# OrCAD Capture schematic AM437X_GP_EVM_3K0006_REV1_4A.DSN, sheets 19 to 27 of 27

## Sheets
19 Pg27: Power Monitor: size C
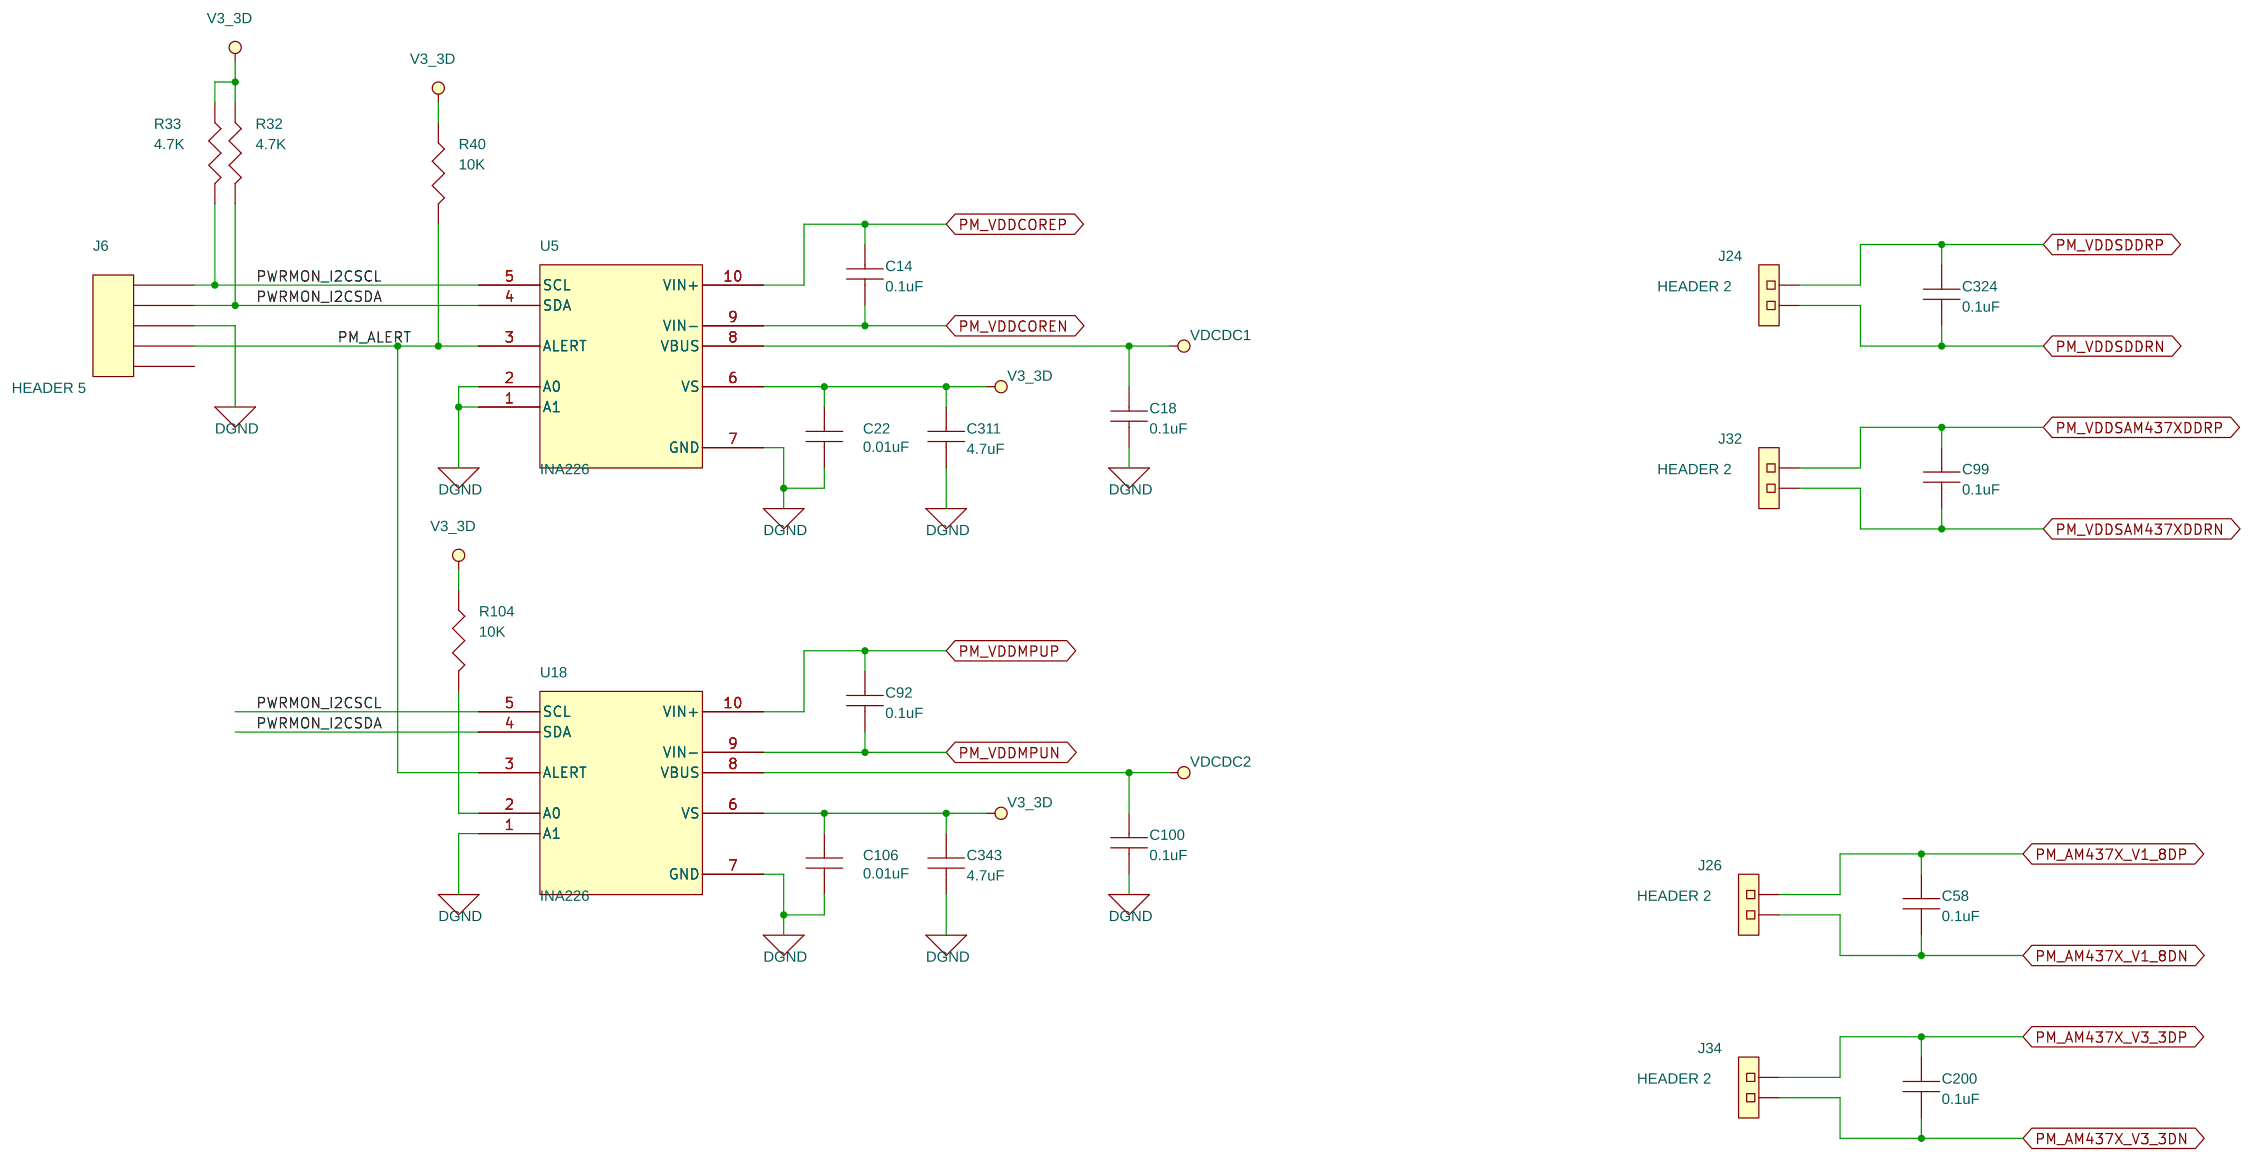
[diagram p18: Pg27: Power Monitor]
20 Pg19: Wireless COM8: size C
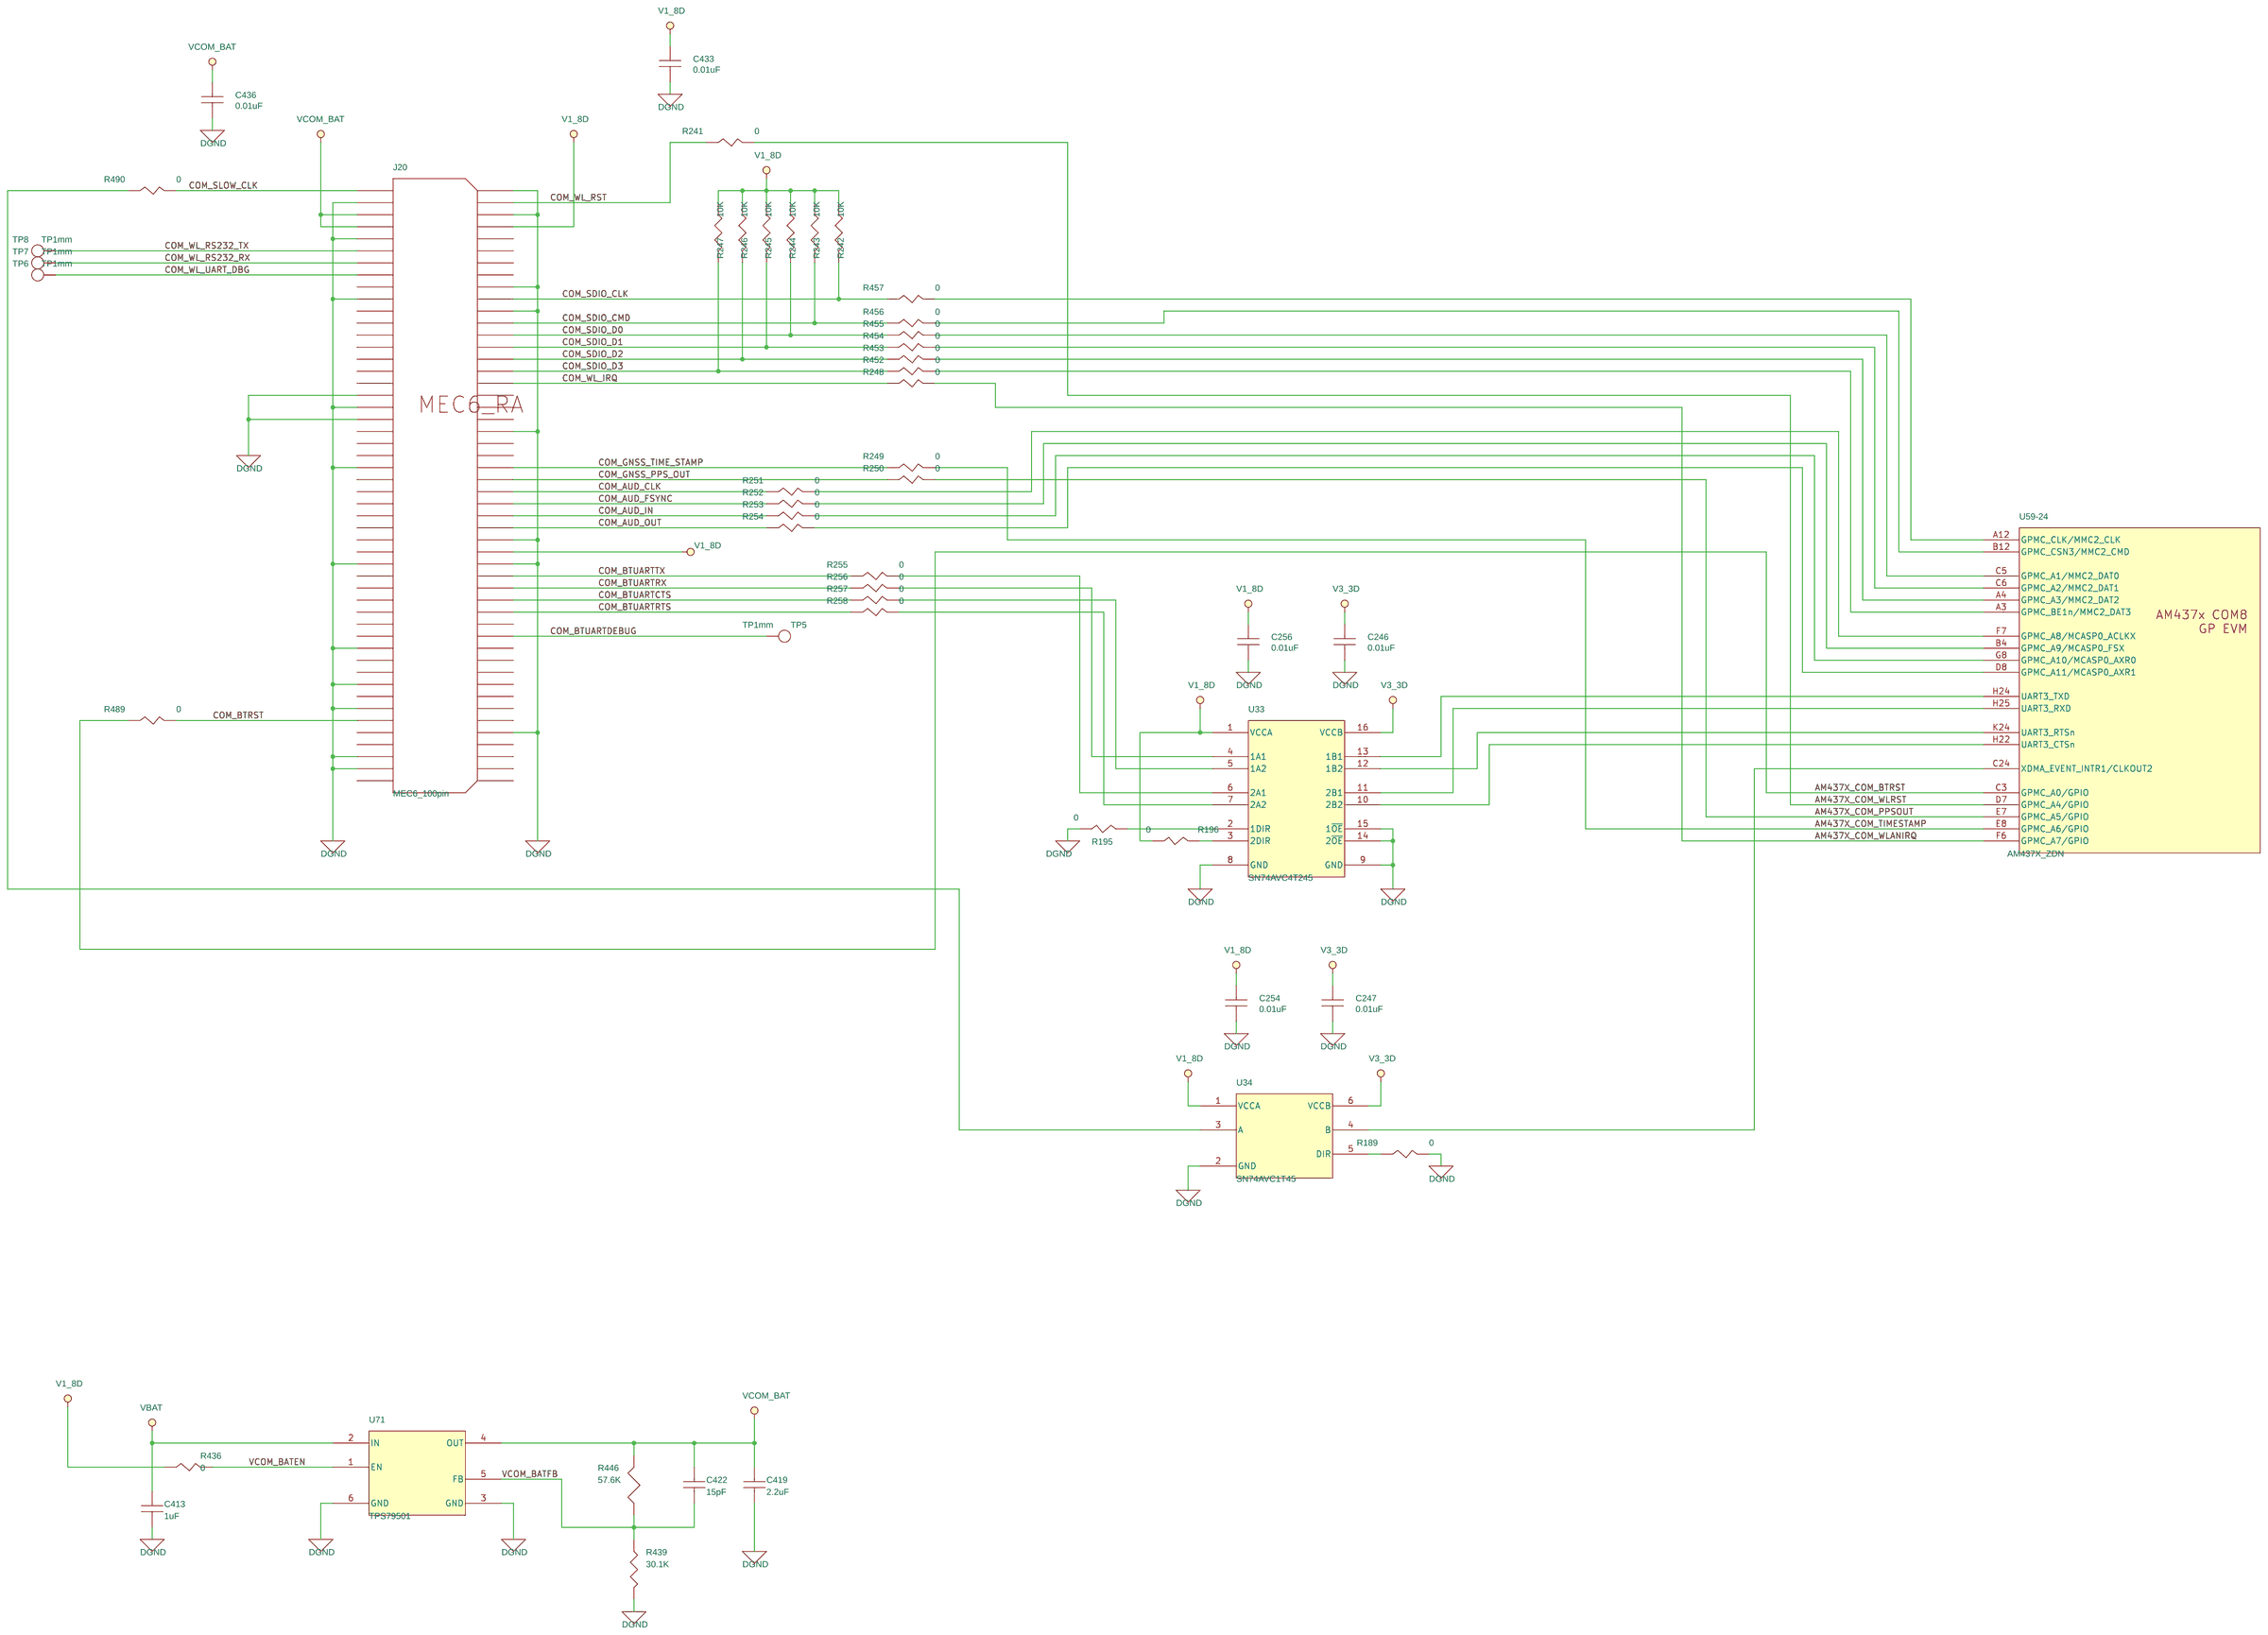
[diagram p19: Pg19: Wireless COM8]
21 Pg04: Power Supply - PMIC: size C
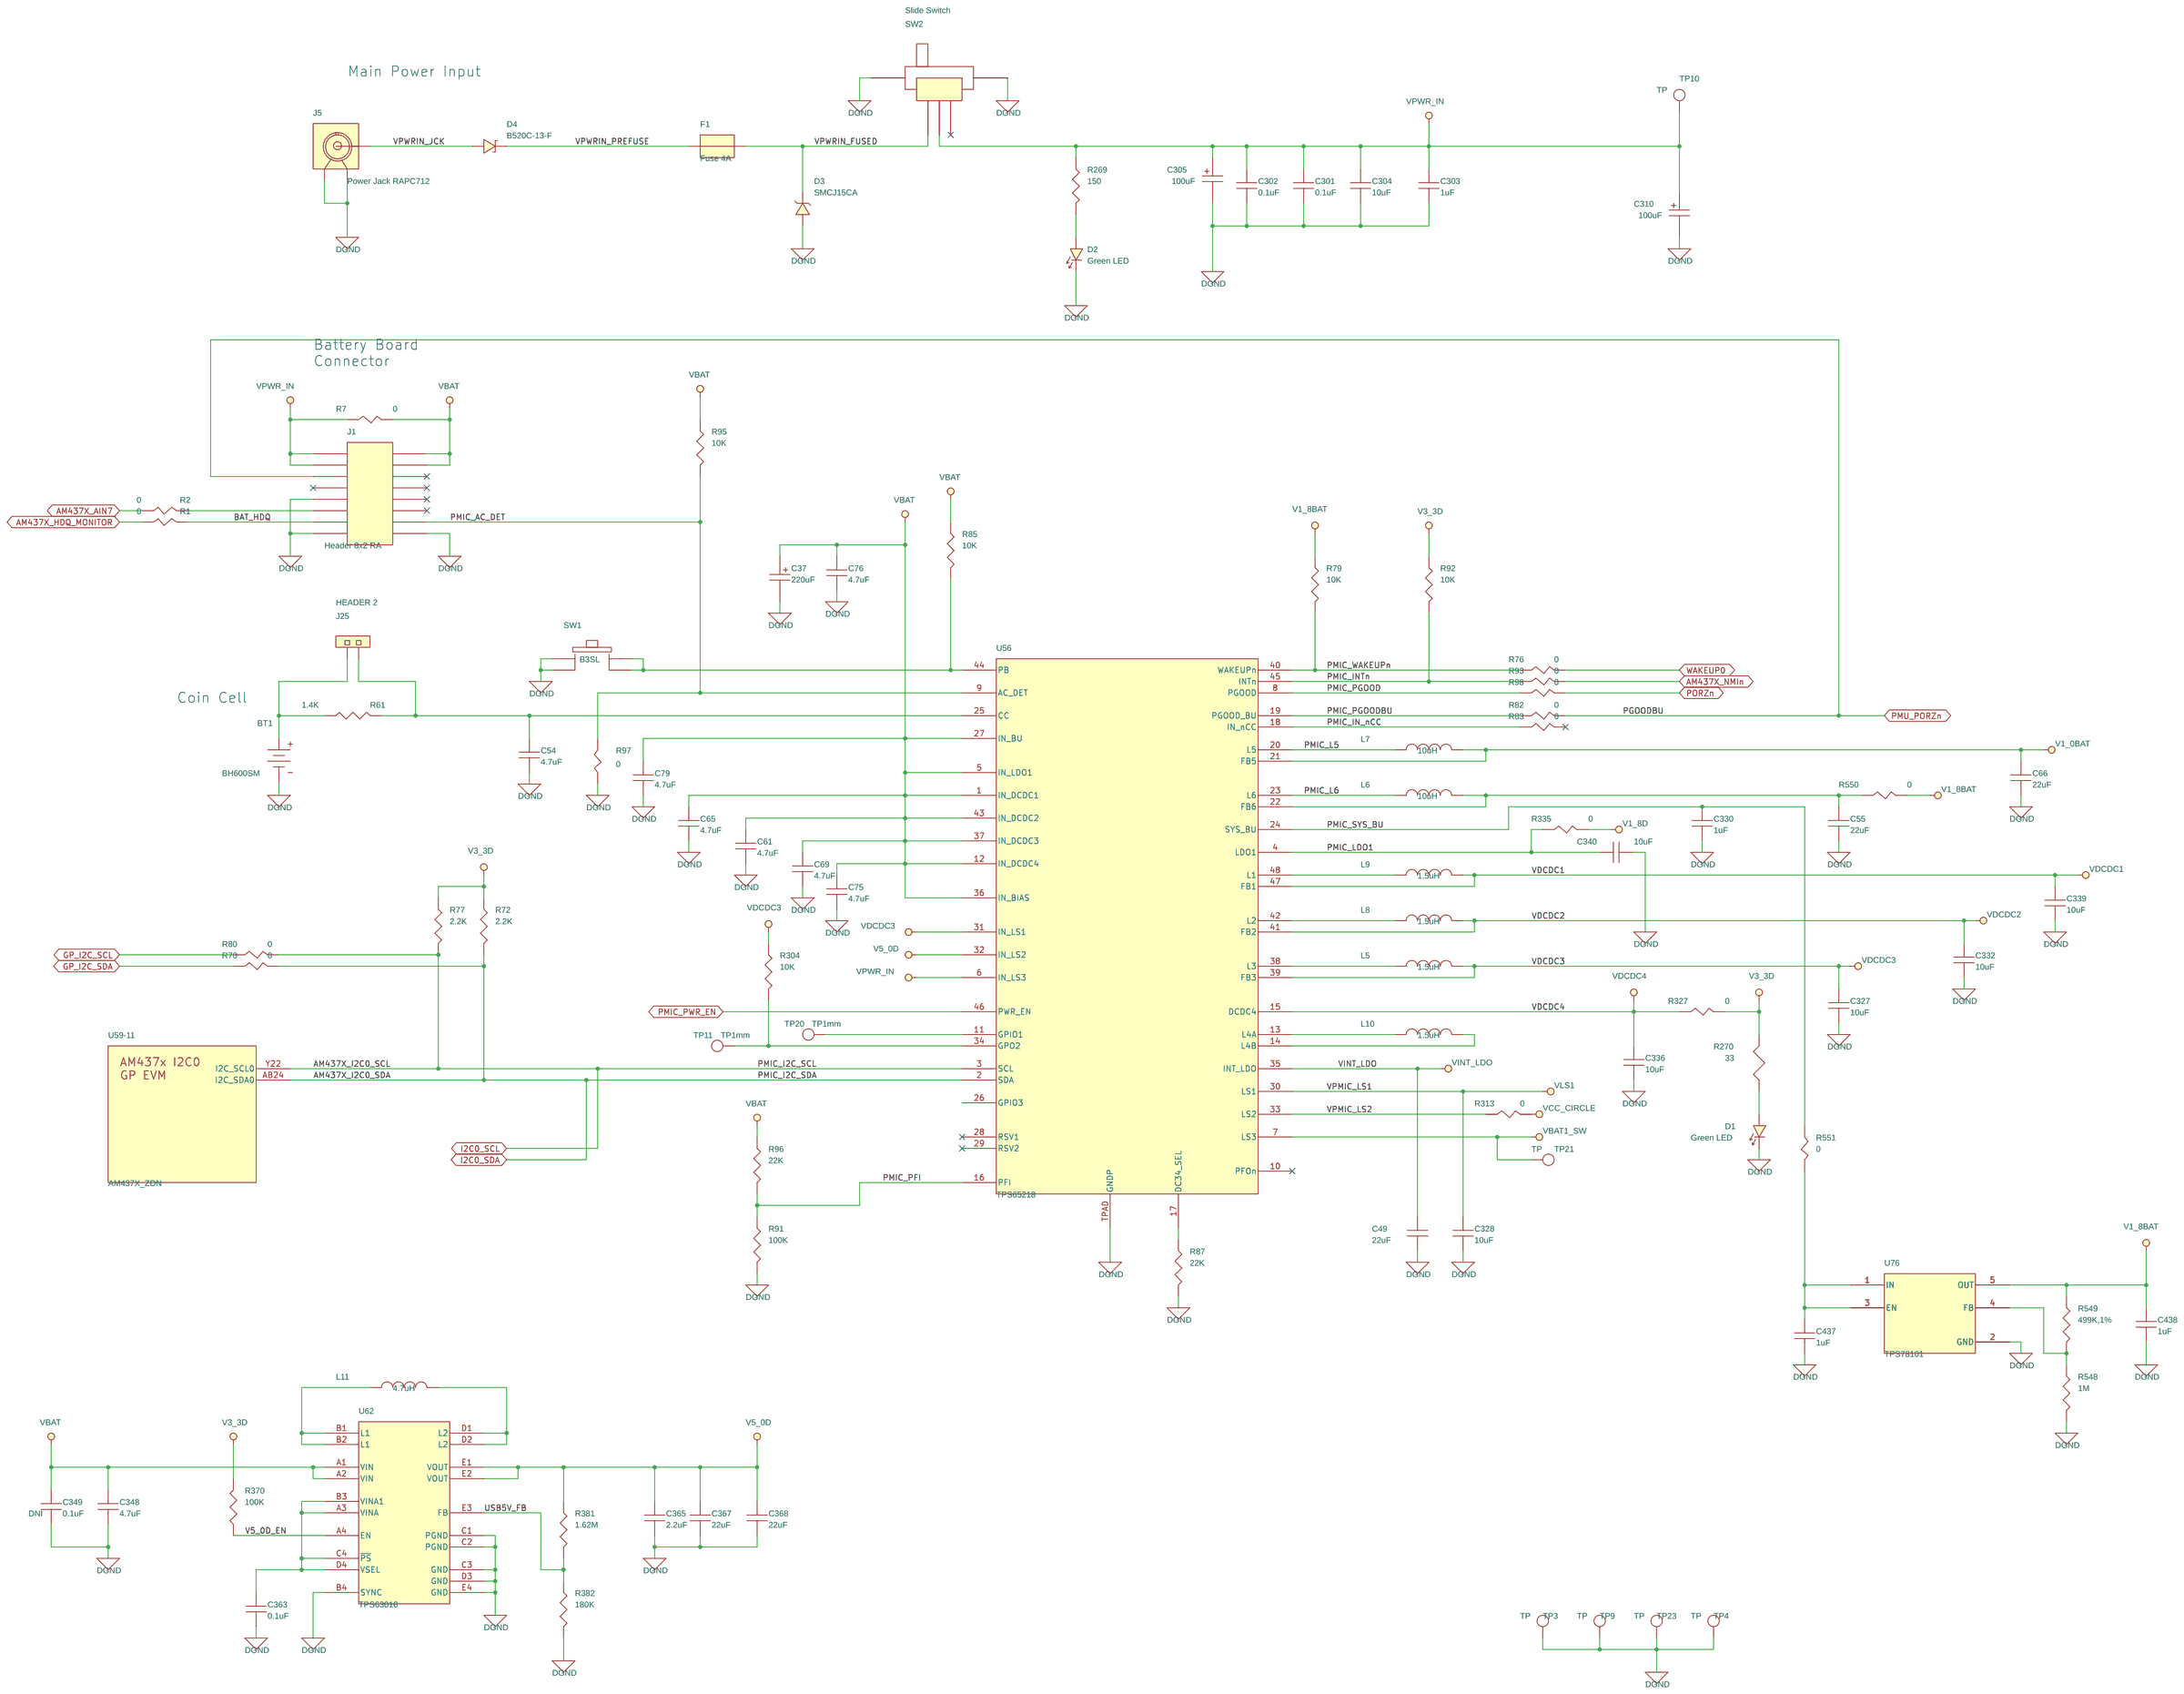
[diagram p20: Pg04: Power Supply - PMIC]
22 Pg02: Processor subsystem: size C
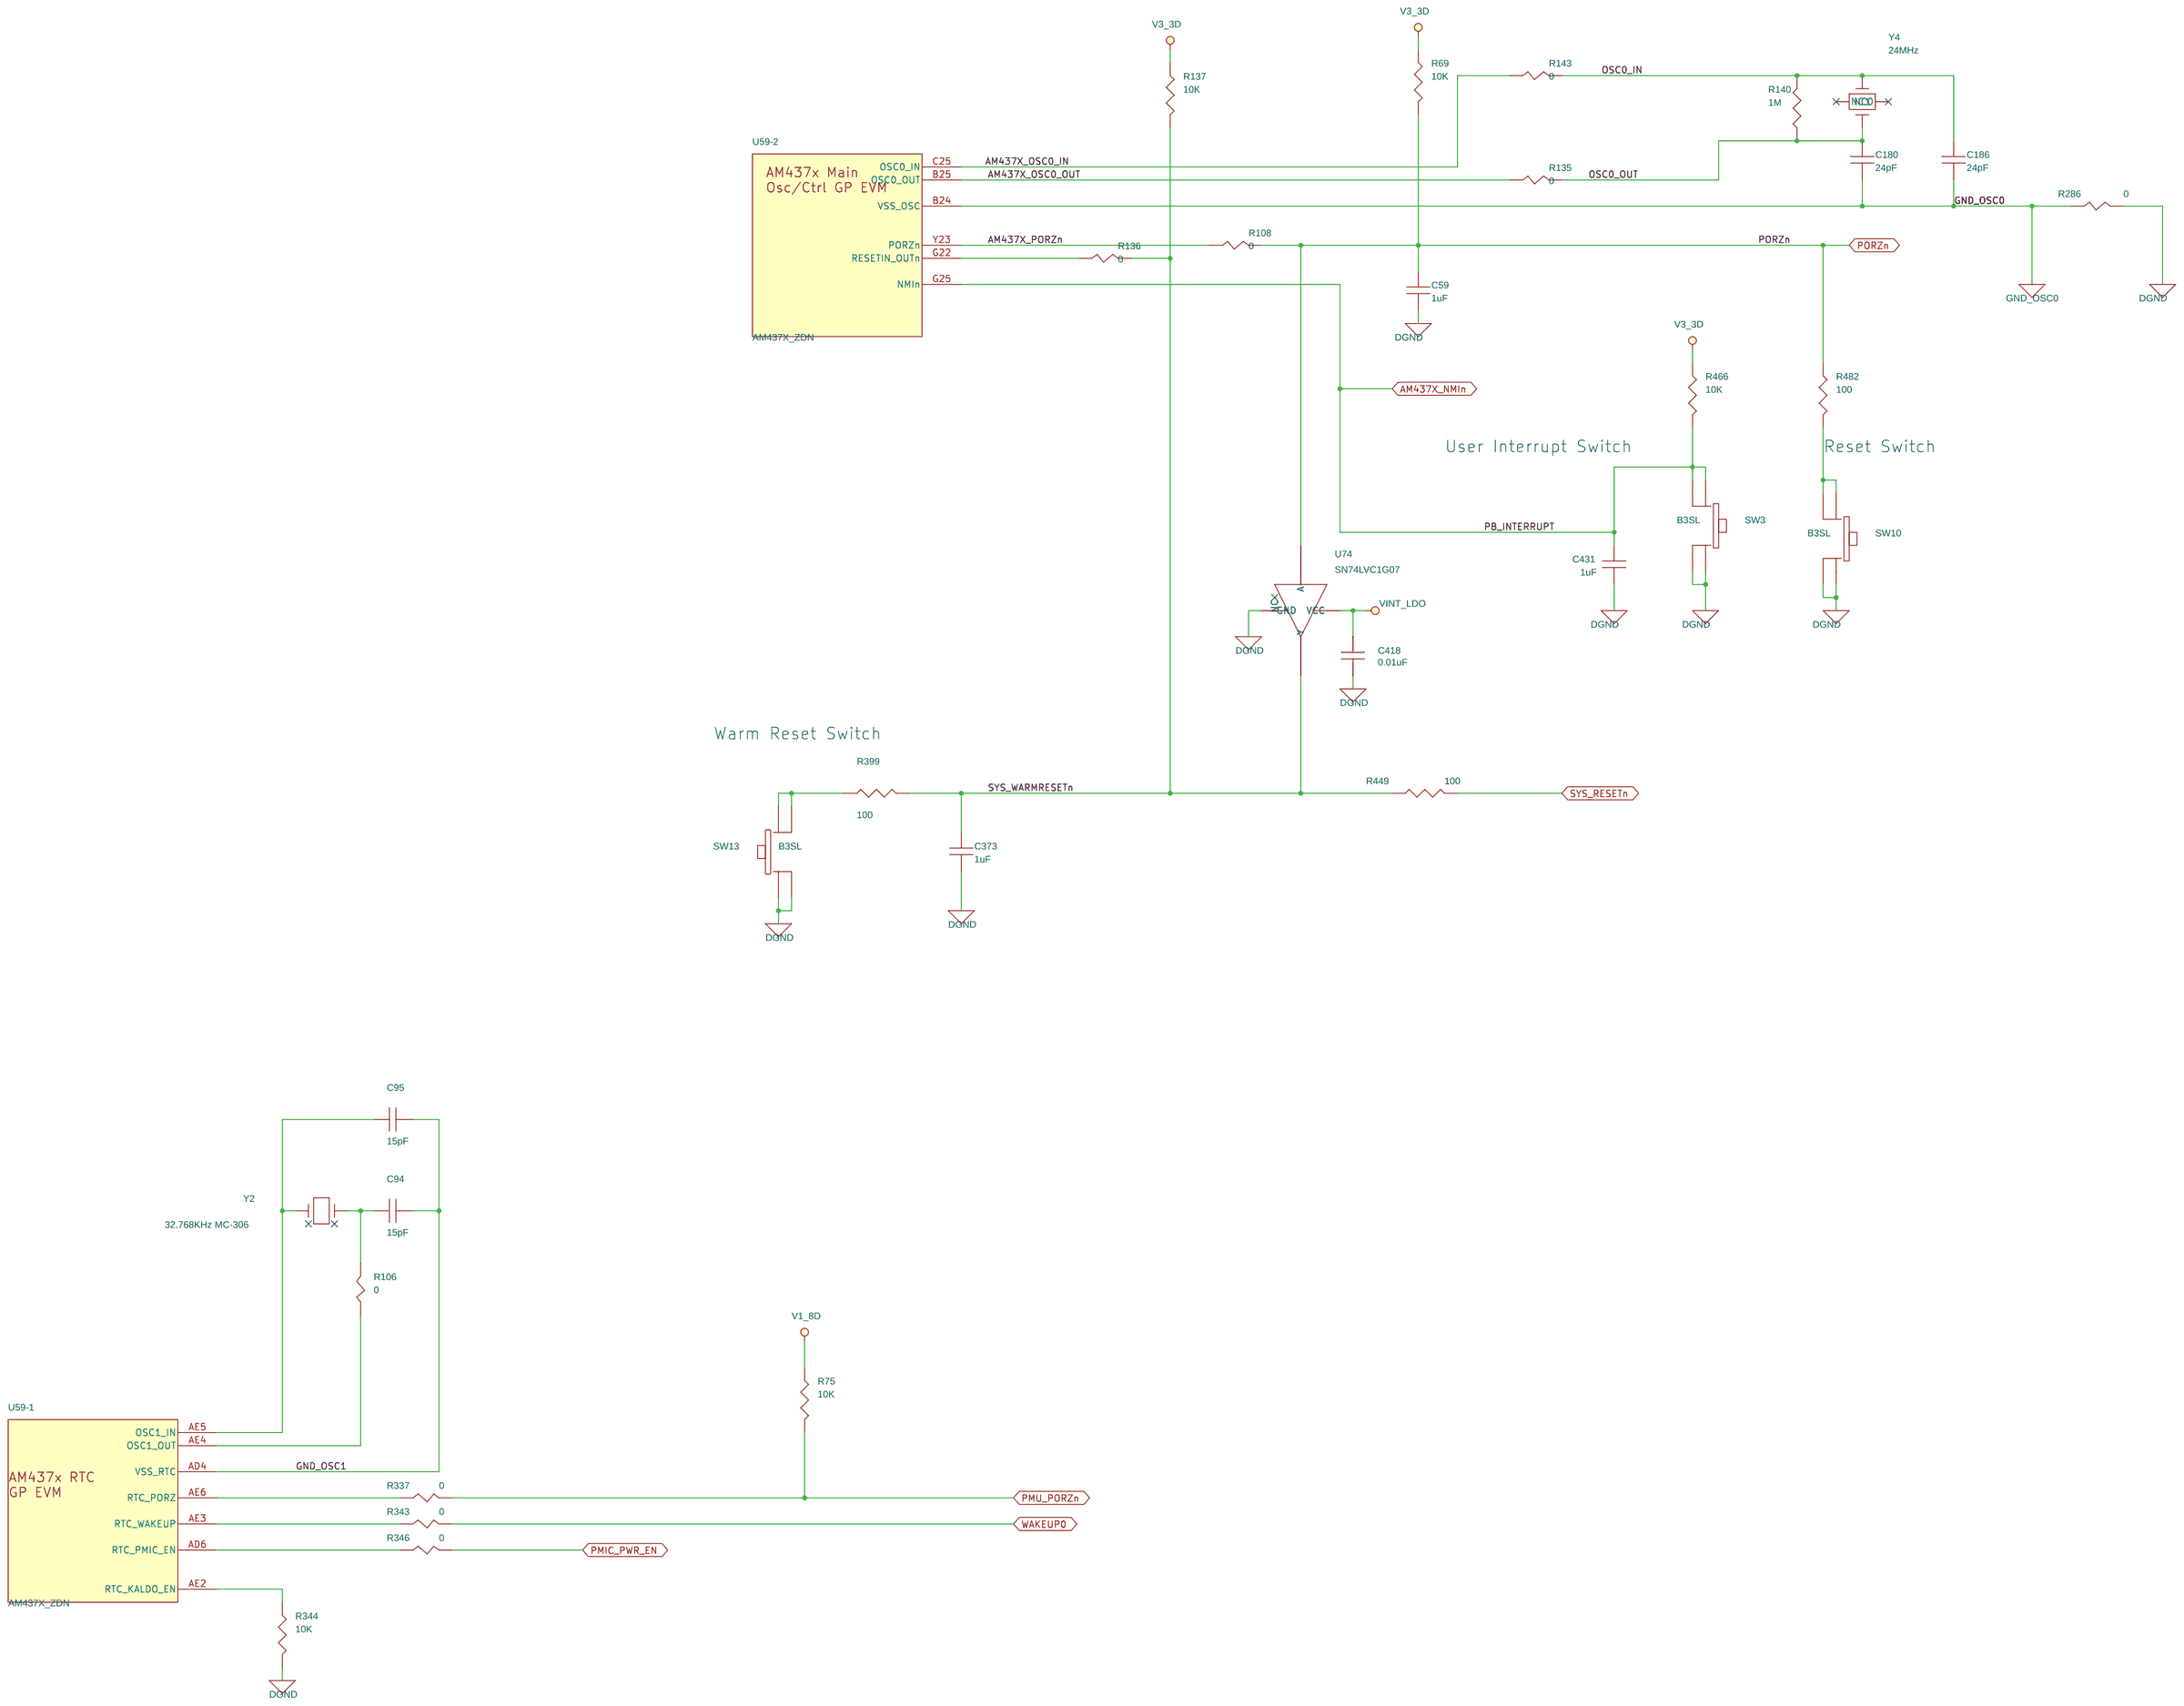
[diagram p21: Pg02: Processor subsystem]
23 Pg08: SDMMC0 Interface: size C
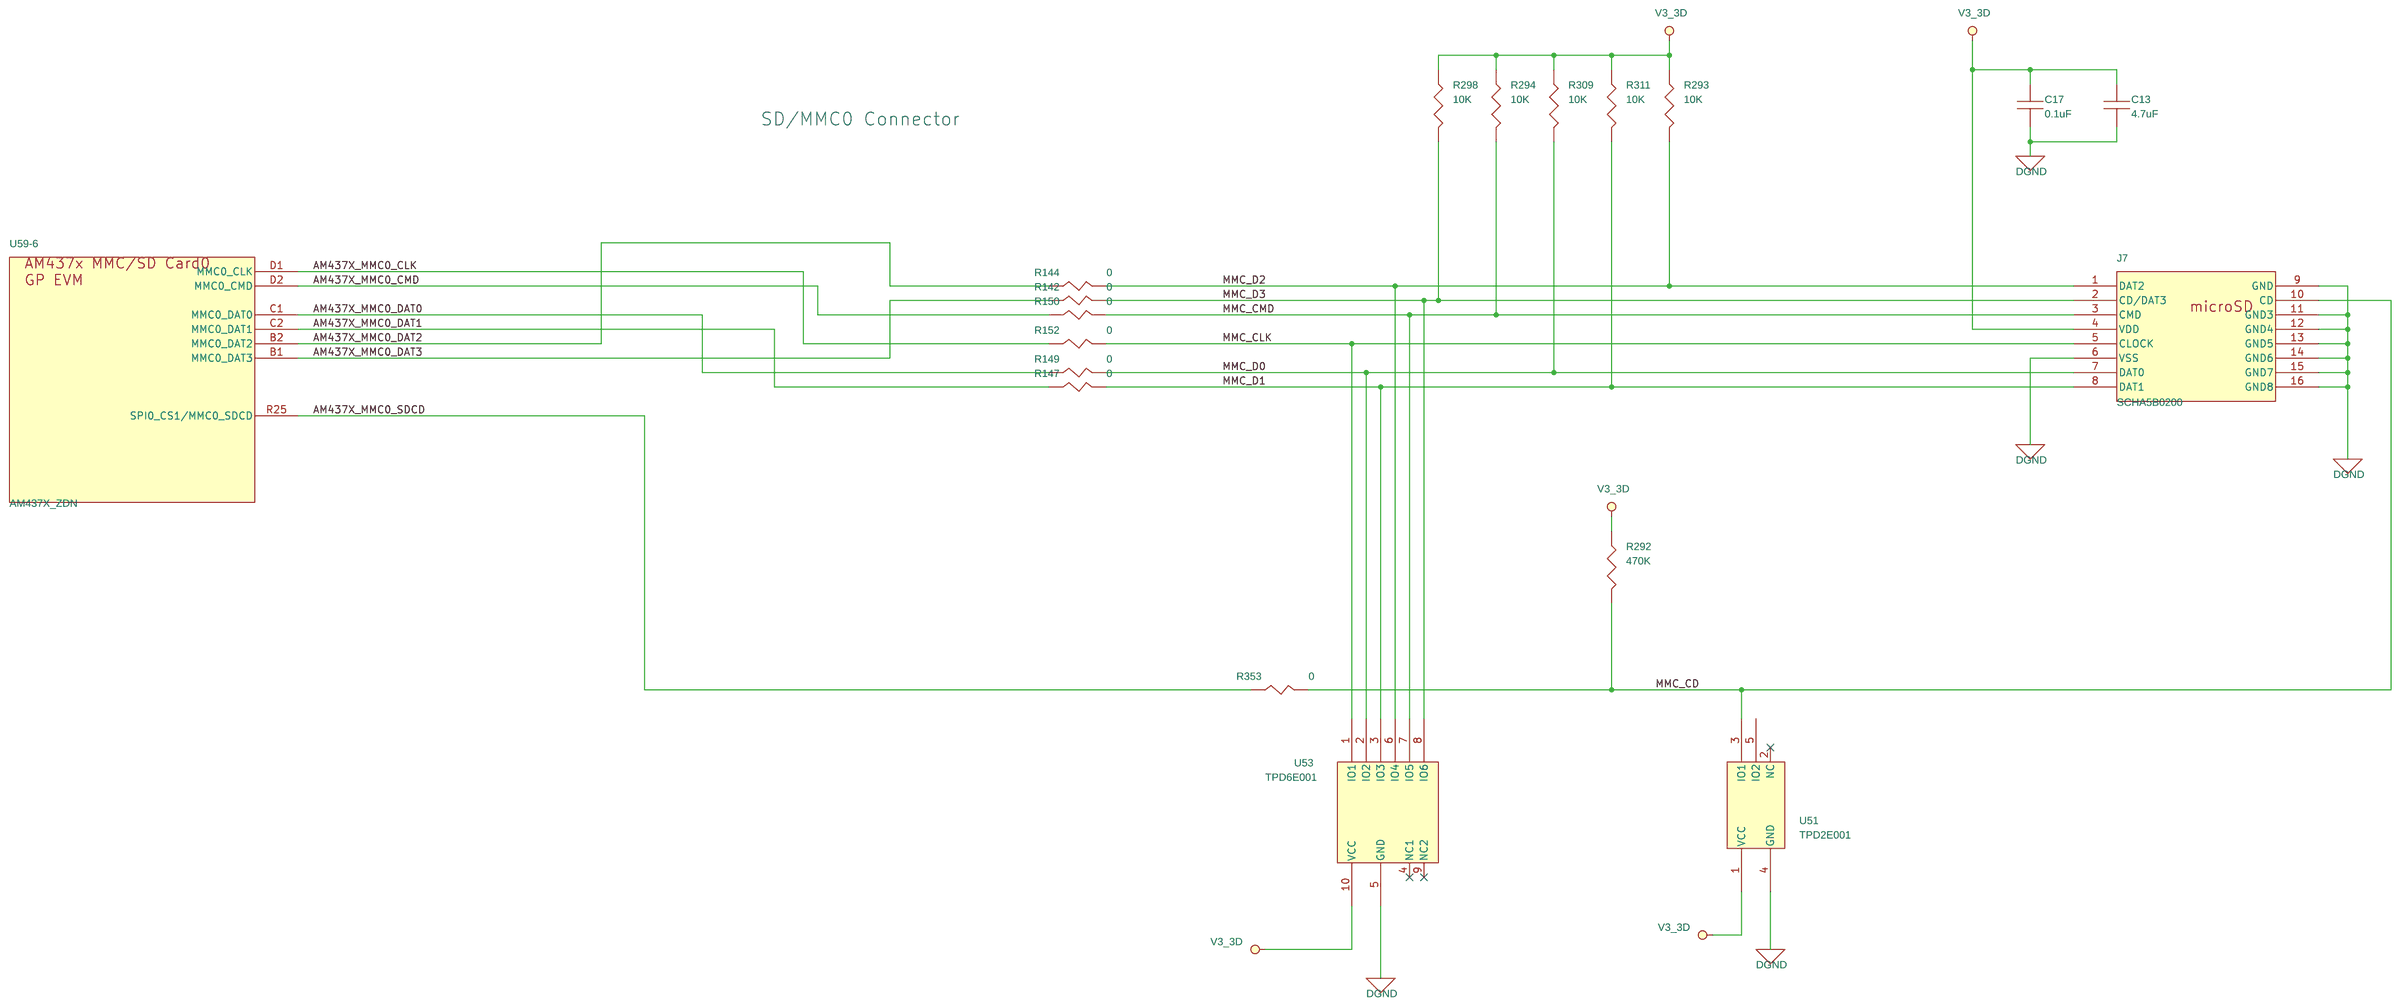
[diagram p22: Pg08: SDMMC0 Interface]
24 Pg23: Unused pins/GPIO: size C
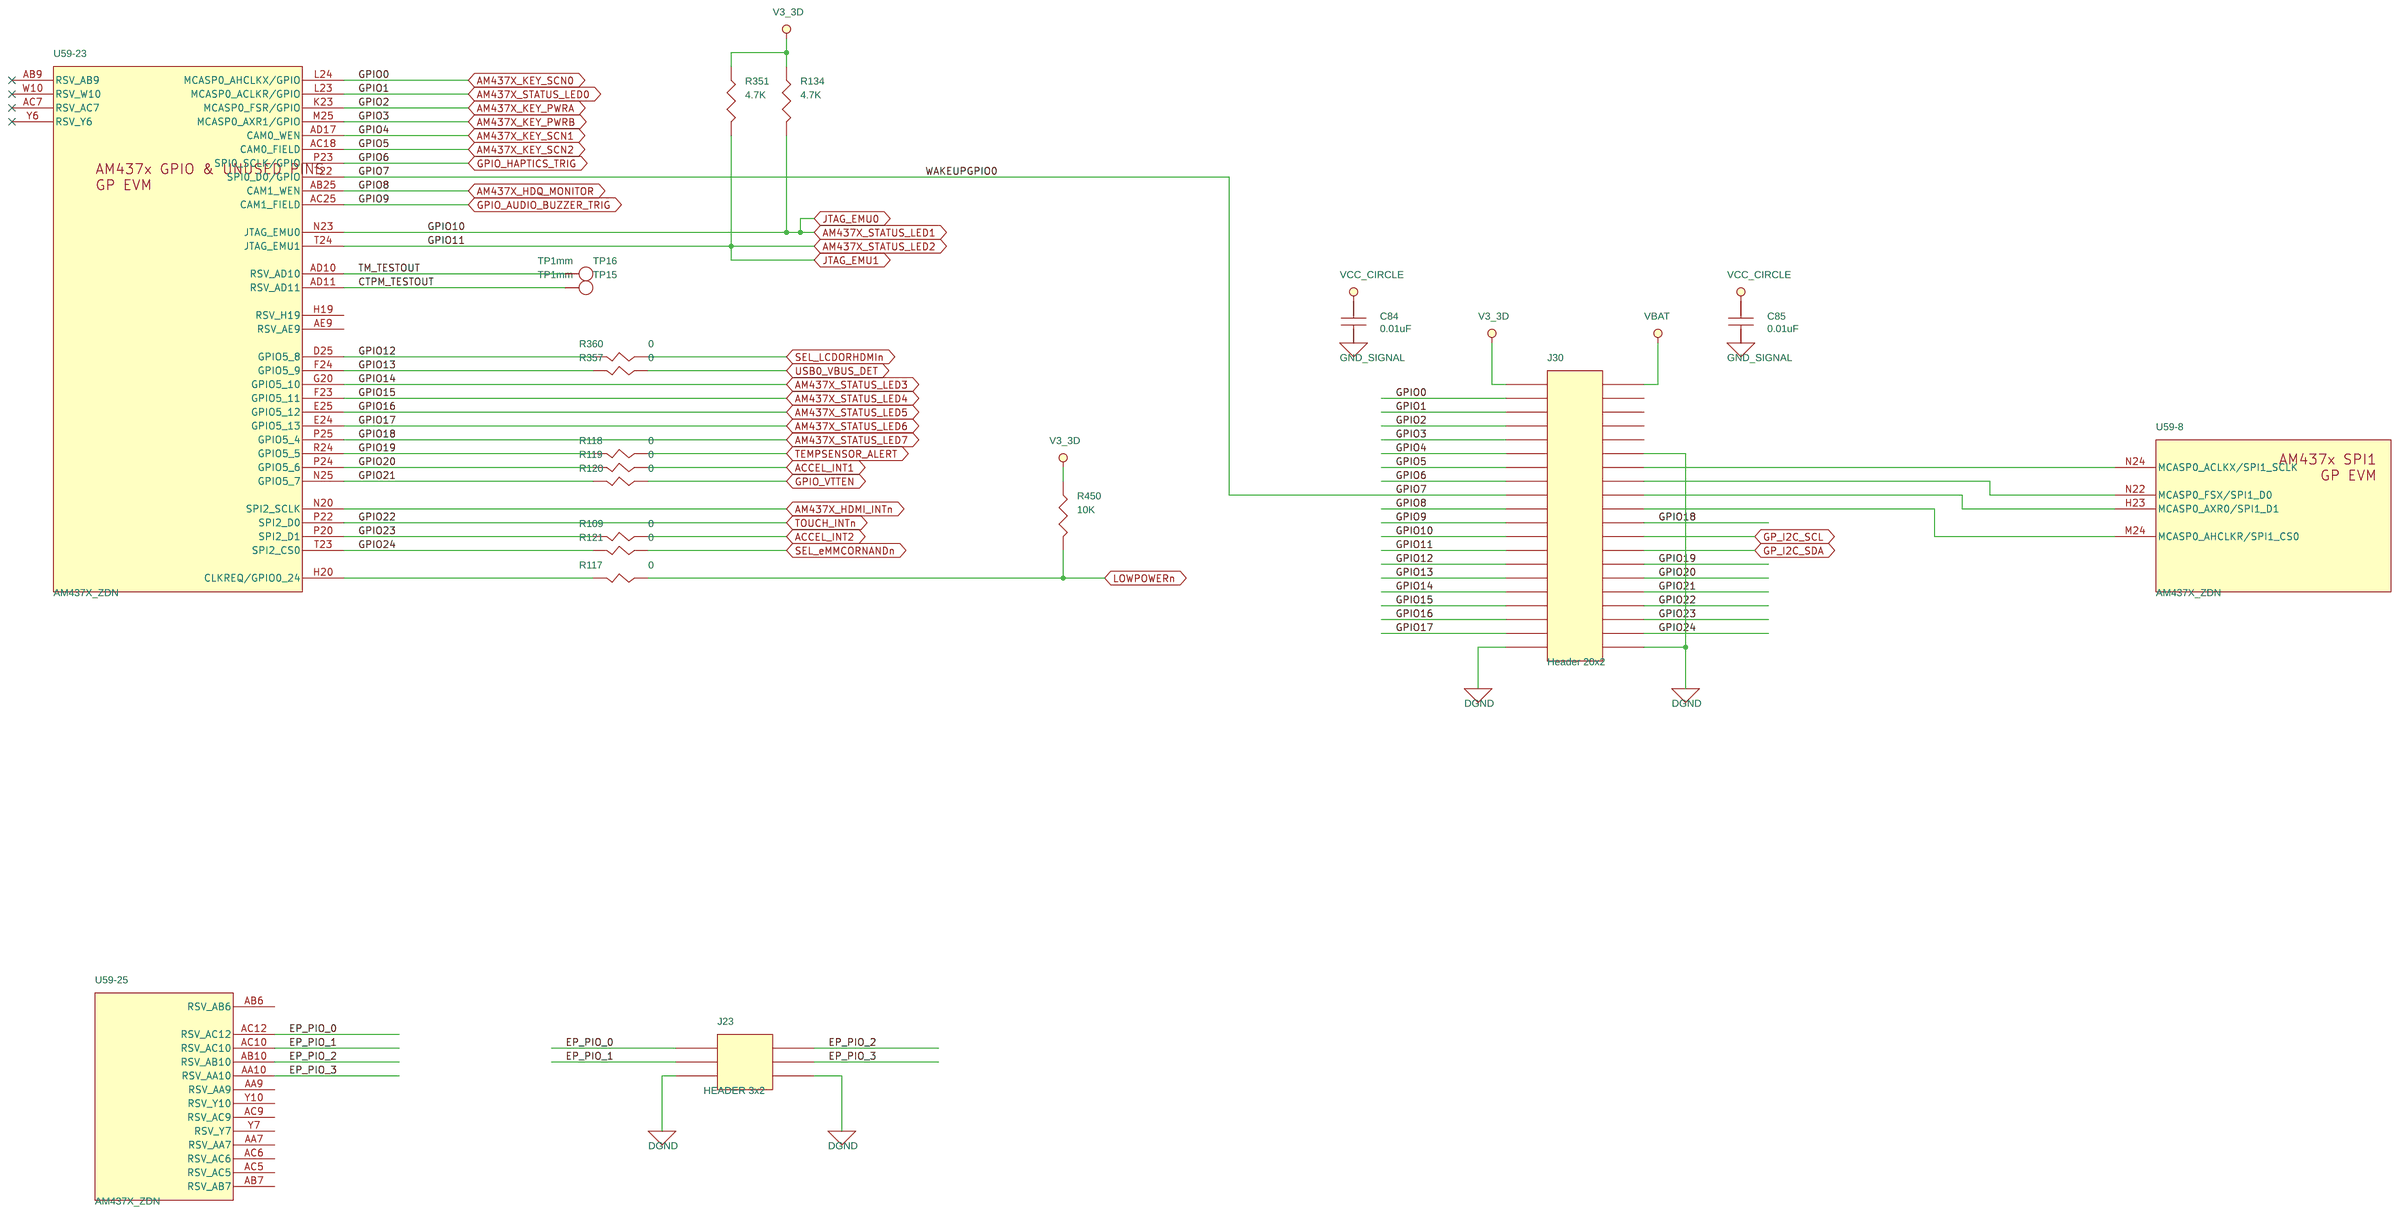
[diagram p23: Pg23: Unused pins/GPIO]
25 Pg05: NAND Flash Memory & eMMC: size C
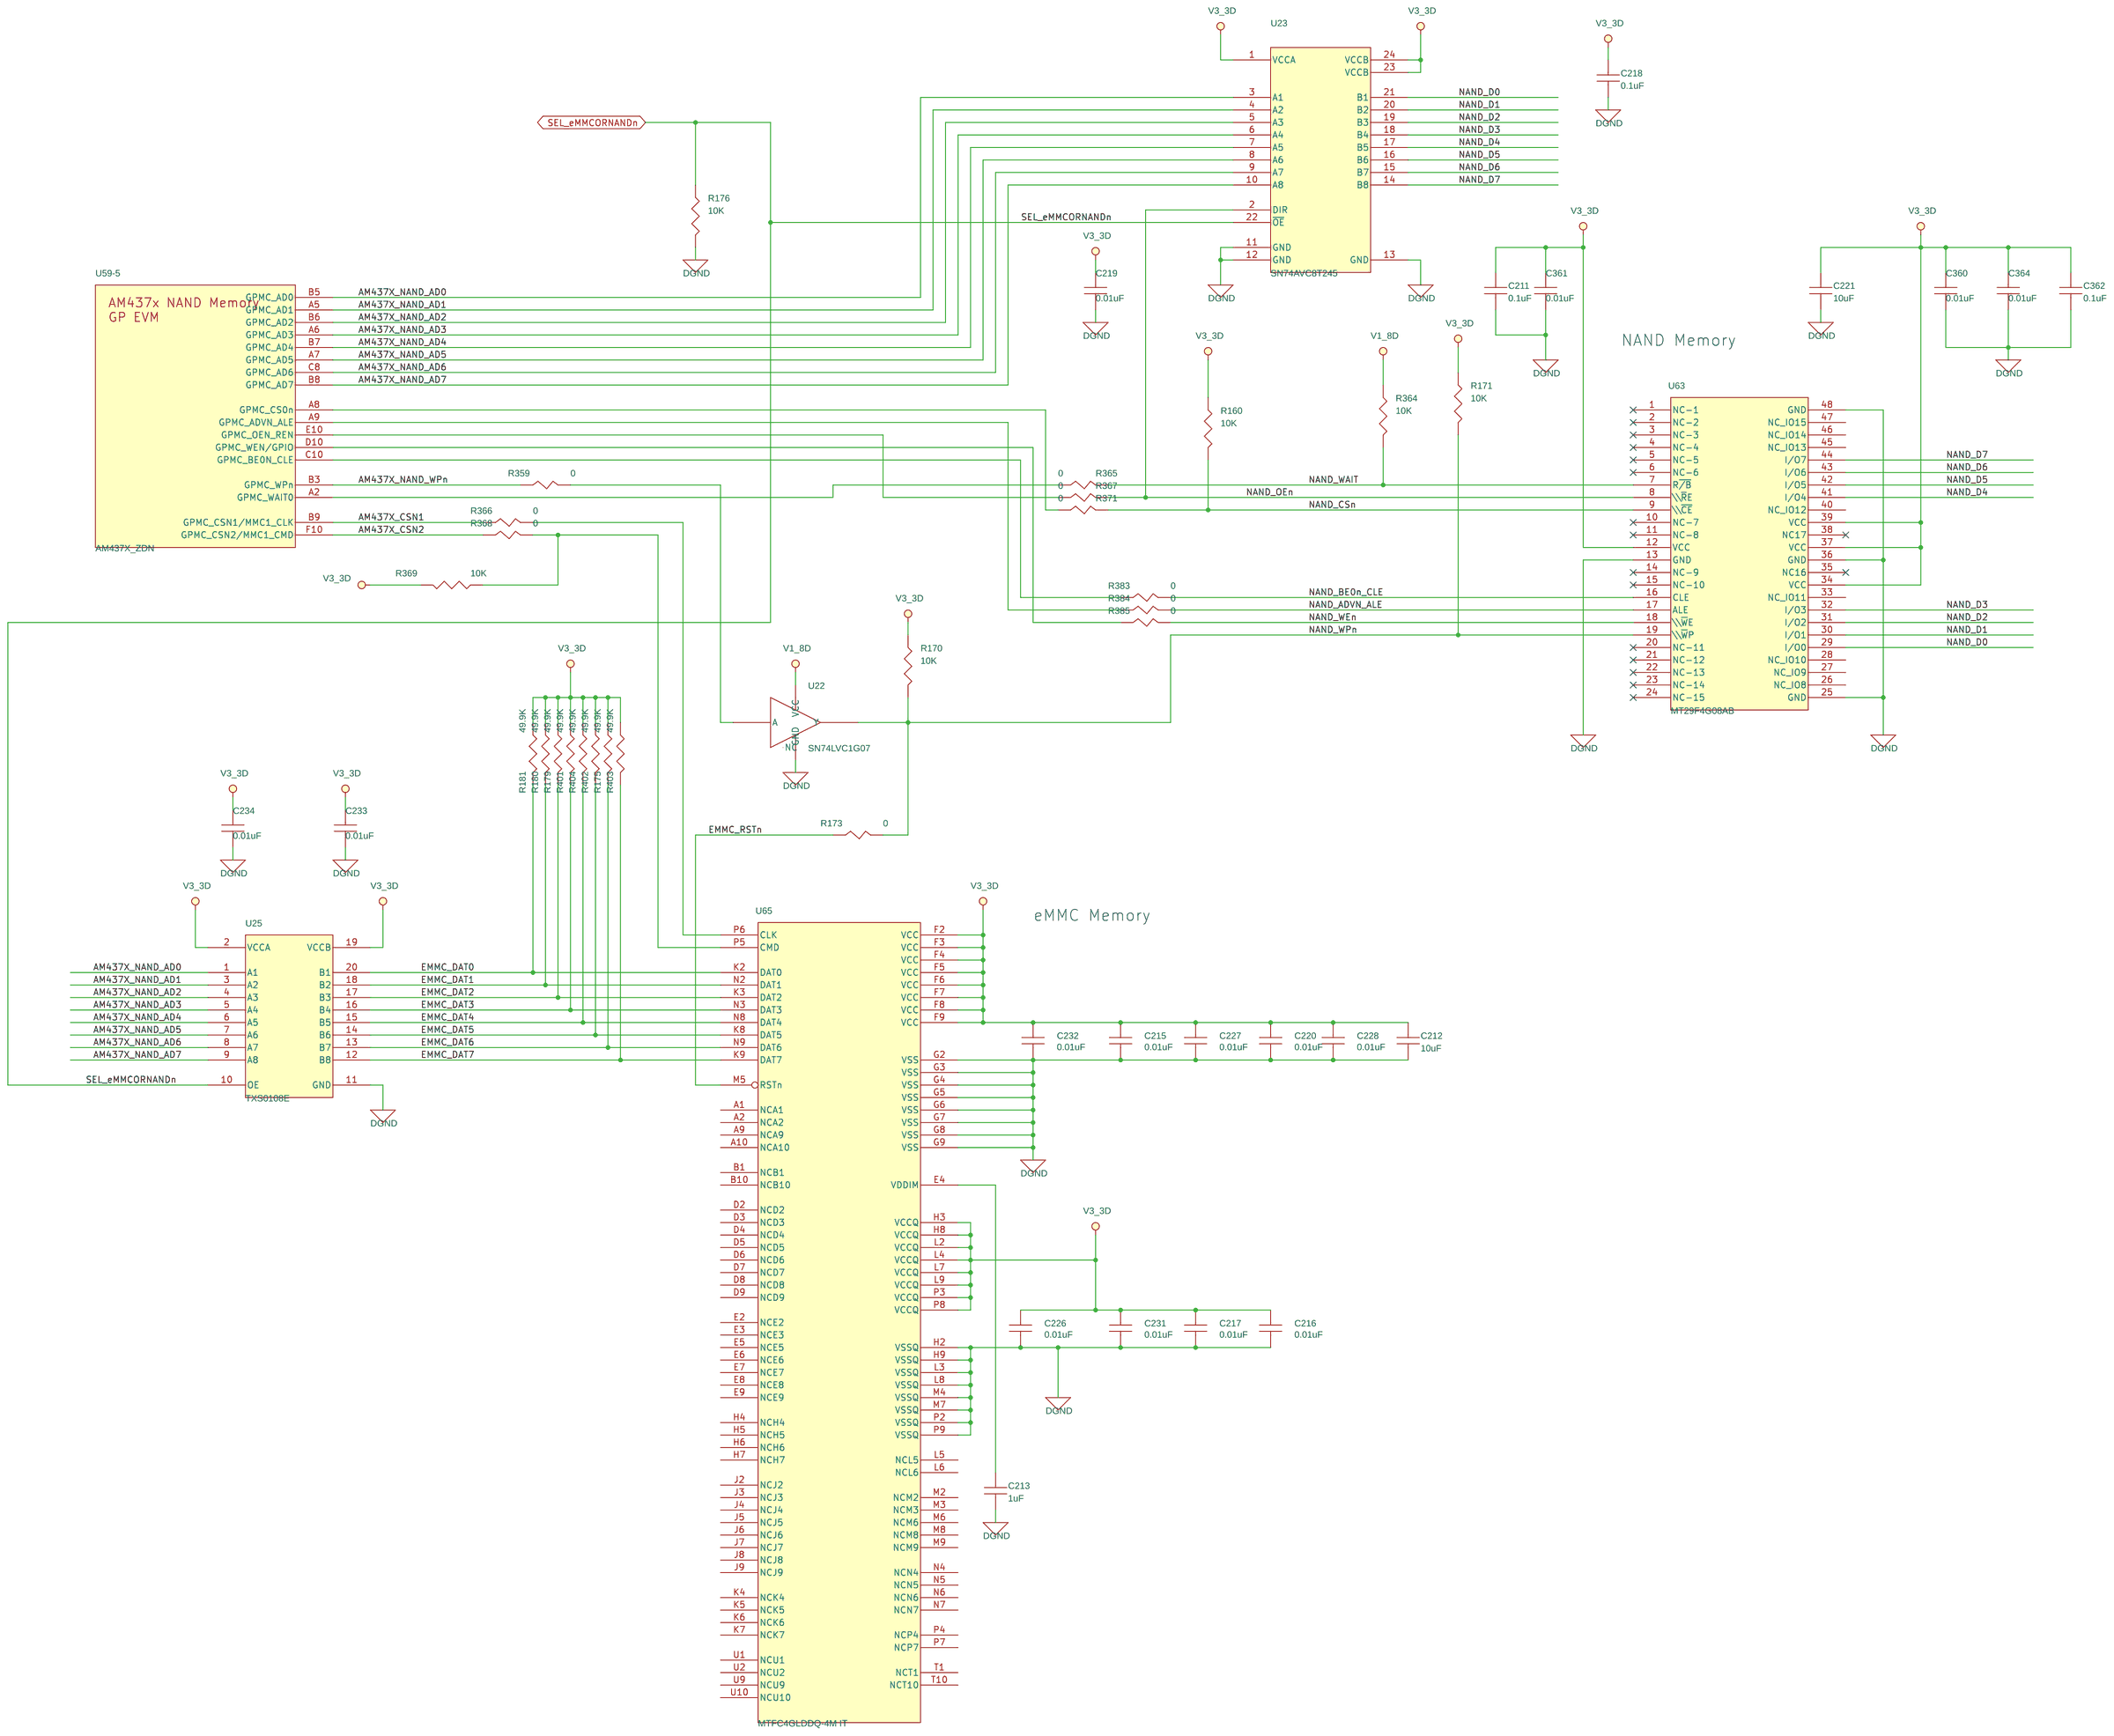
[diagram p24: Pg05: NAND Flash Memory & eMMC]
26 Pg20: Tamper Oscillator/Ctrl: size C
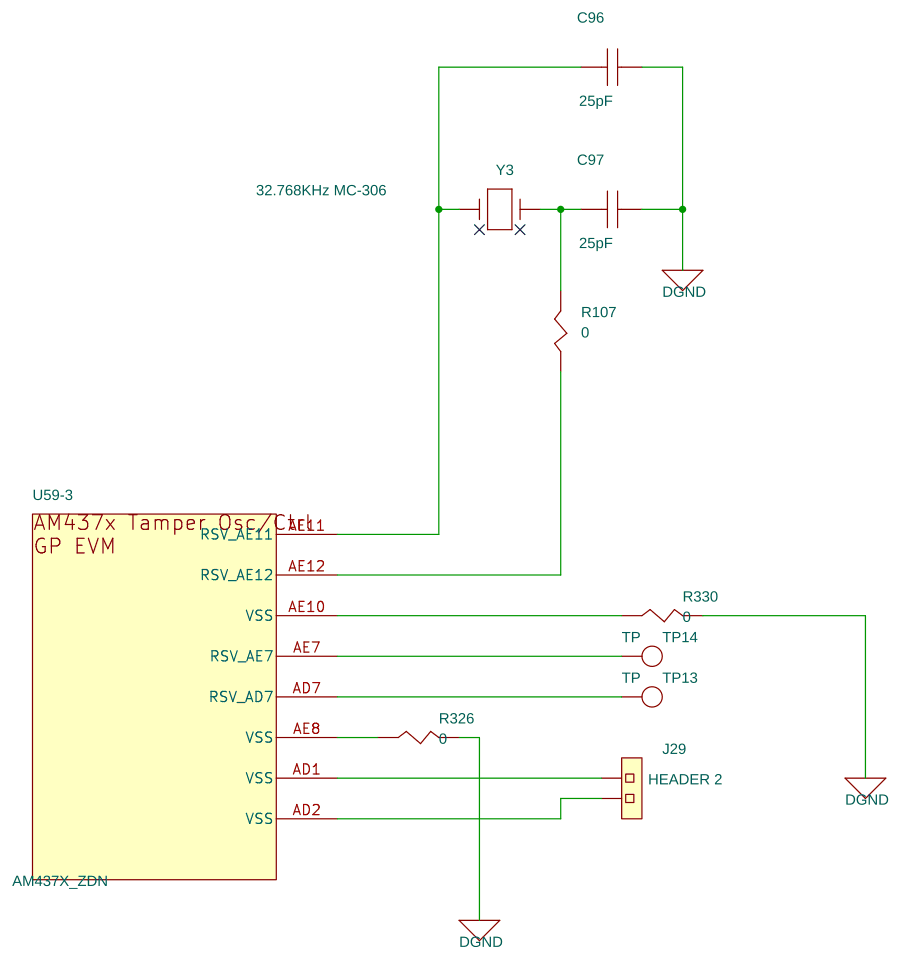
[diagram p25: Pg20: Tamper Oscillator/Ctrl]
27 Pg10: Sensors, Buzzer, Haptics: size C
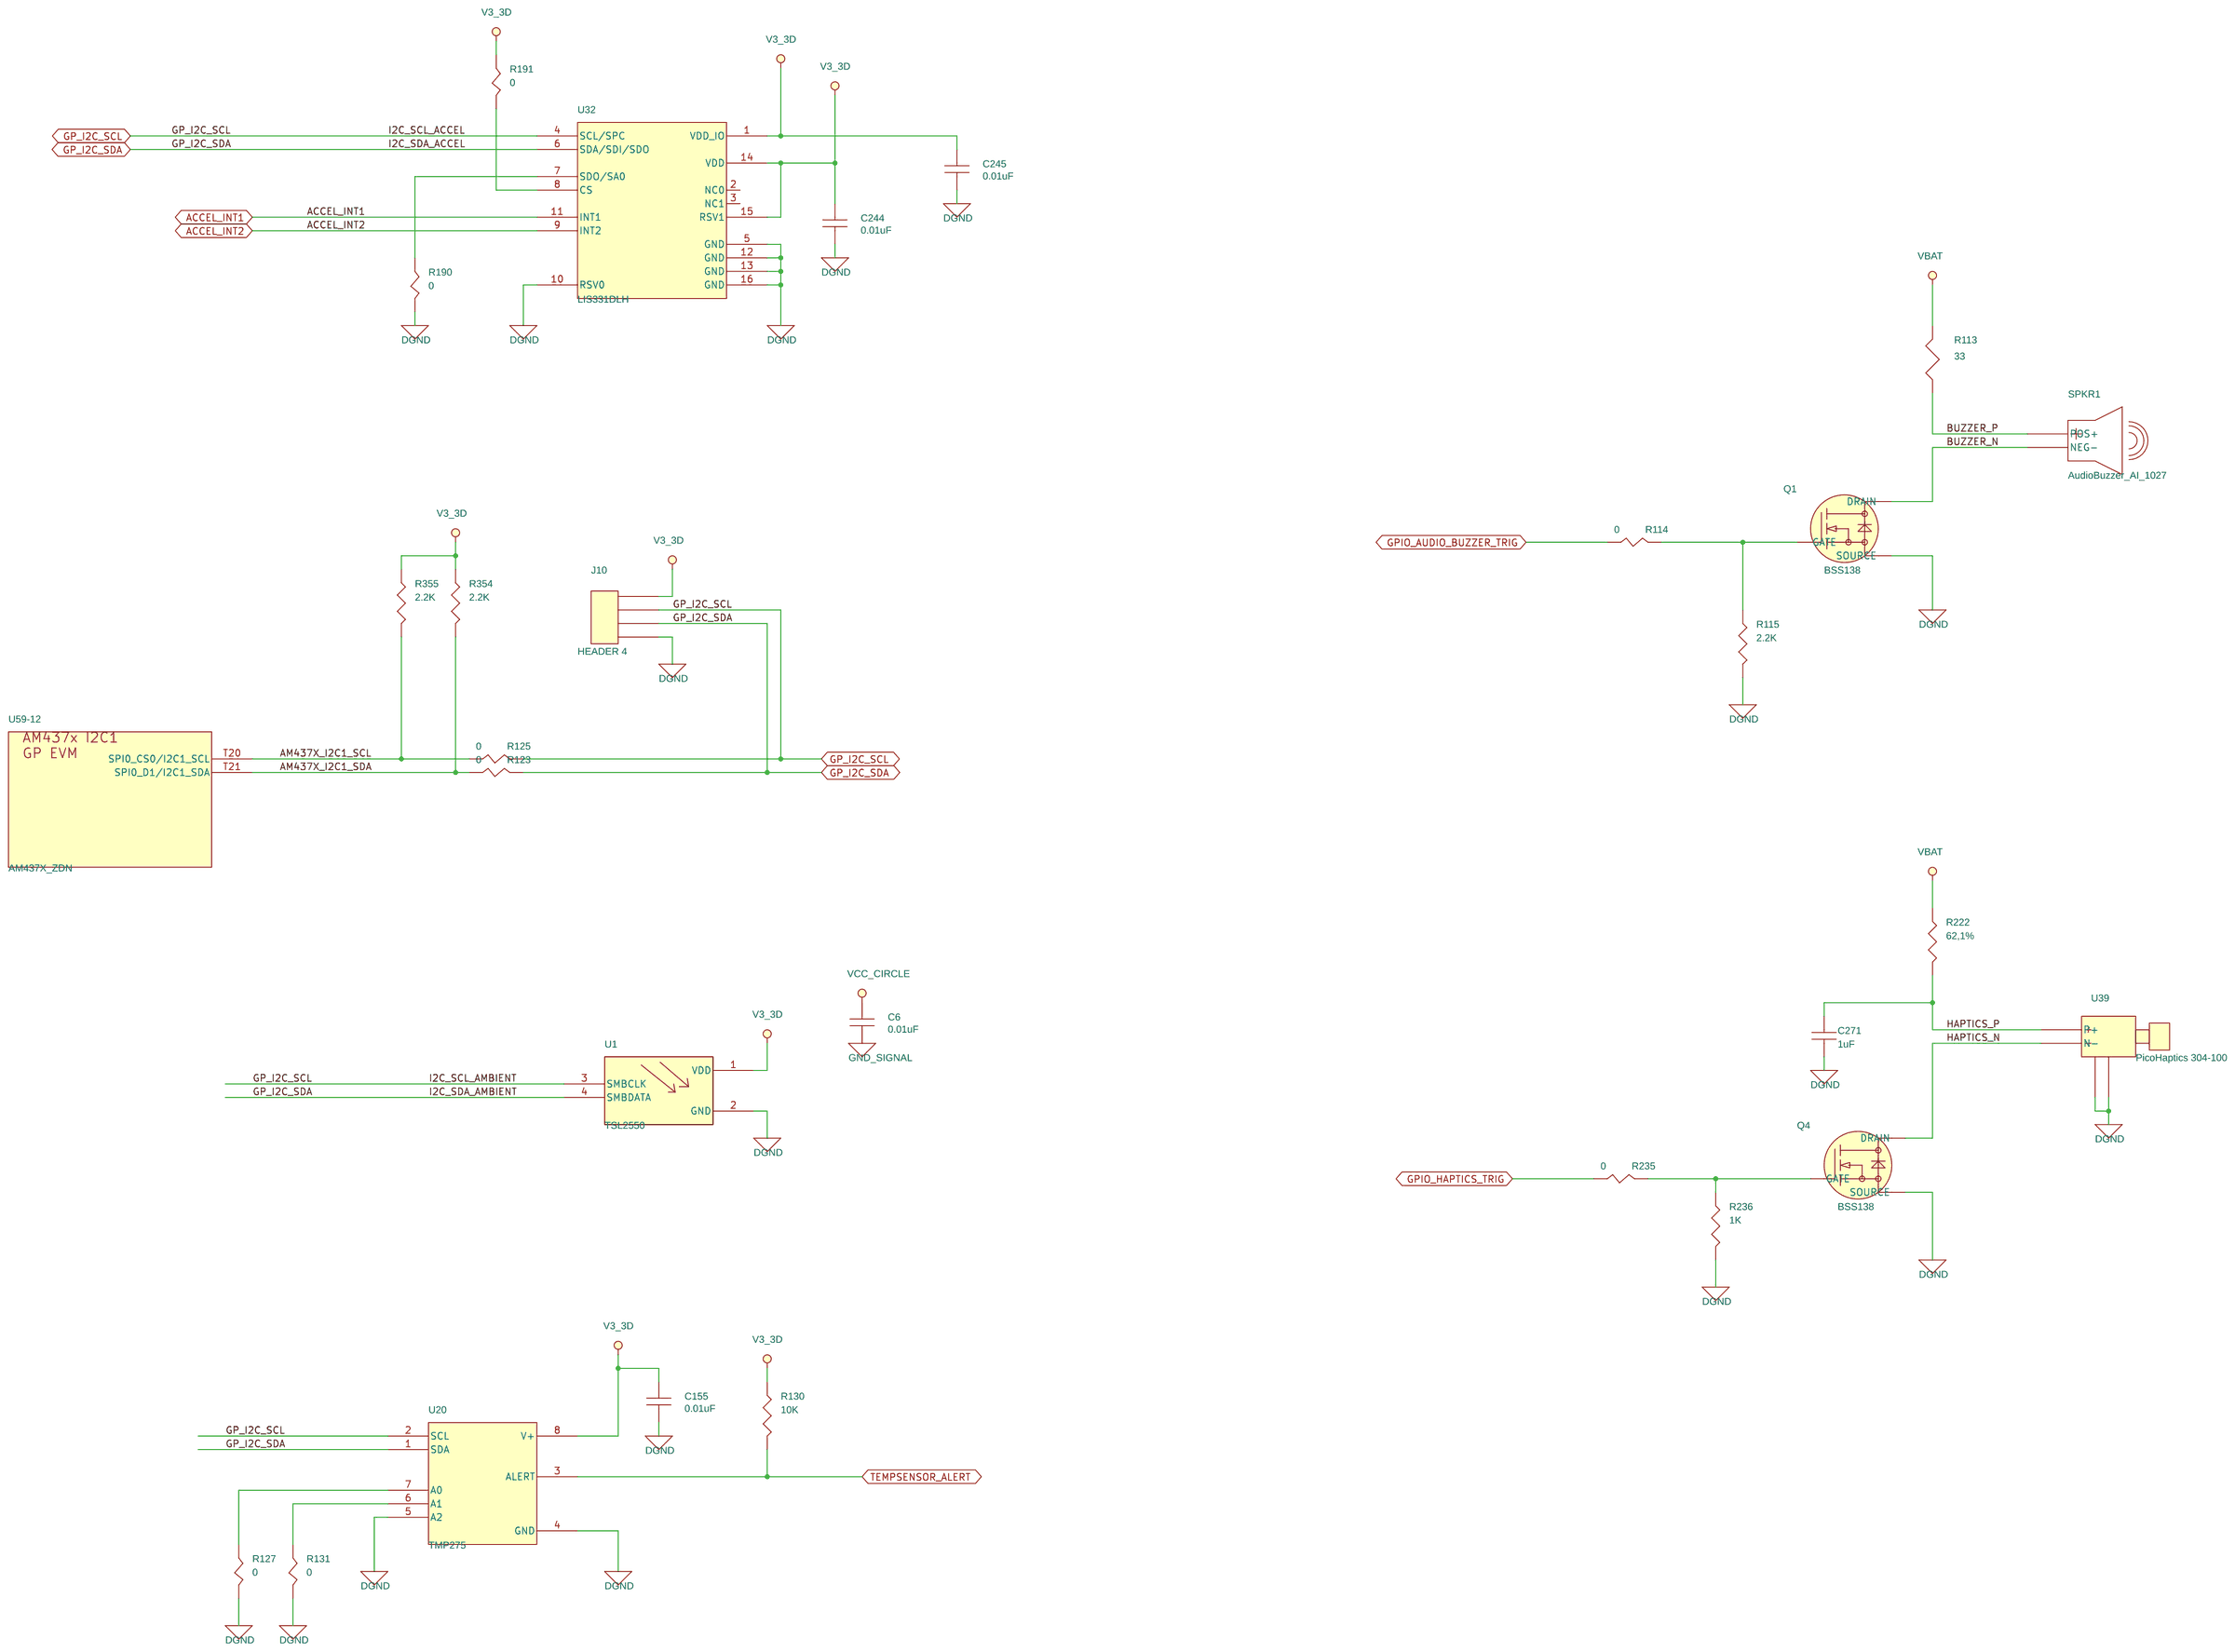
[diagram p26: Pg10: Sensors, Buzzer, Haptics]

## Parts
sheet Pg02: Processor subsystem
C59  1uF  [SM-7351-CAP-0402]
C94  15pF  [SM-7351-CAP-0402]
C95  15pF  [SM-7351-CAP-0402]
C180  24pF  [SM-7351-CAP-0402]
C186  24pF  [SM-7351-CAP-0402]
C373  1uF  [SM-7351-CAP-0402]
C418  0.01uF  [SM-7351-CAP-0402]
C431  1uF  [SM-7351-CAP-0402]
R69  10K  [SM-7351-RES-0402]
R75  10K  [SM-7351-RES-0402]
R106  0  [SM-7351-RES-0402]
R108  0  [SM-7351-RES-0402]
R135  0  [SM-7351-RES-0402]
R136  0  [SM-7351-RES-0402]
R137  10K  [SM-7351-RES-0402]
R140  1M  [SM-7351-RES-0402]
R143  0  [SM-7351-RES-0402]
R286  0  [SM-7351-RES-0402]
R337  0  [SM-7351-RES-0402]
R343  0  [SM-7351-RES-0402]
R344  10K  [SM-7351-RES-0402]
R346  0  [SM-7351-RES-0402]
R399  100  [SM-7351-RES-0402]
R449  100  [SM-7351-RES-0402]
R466  10K  [SM-7351-RES-0402]
R482  100  [SM-7351-RES-0402]
SW3  B3SL  [SW_B3SL-1022P]
SW10  B3SL  [SW_B3SL-1022P]
SW13  B3SL  [SW_B3SL-1022P]
U74  SN74LVC1G07  [SC70-5-43M]
Y2  32.768KHz MC-306  [MC-306]
Y4  24MHz  [XTAL2X3-30M]
sheet Pg04: Power Supply - PMIC
BT1  BH600SM  [bh600sm]
C37  220uF  [smd7343-122m]
C49  22uF  [SM-7351-CAP-0805]
C54  4.7uF  [SM-7351-CAP-0603]
C55  22uF  [SM-7351-CAP-0603]
C61  4.7uF  [SM-7351-CAP-0603]
C65  4.7uF  [SM-7351-CAP-0603]
C66  22uF  [SM-7351-CAP-0603]
C69  4.7uF  [SM-7351-CAP-0603]
C75  4.7uF  [SM-7351-CAP-0603]
C76  4.7uF  [SM-7351-CAP-0603]
C79  4.7uF  [SM-7351-CAP-0603]
C301  0.1uF  [SM-7351-CAP-0402]
C302  0.1uF  [SM-7351-CAP-0402]
C303  1uF  [SM-7351-CAP-0603]
C304  10uF  [SM-7351-CAP-0805]
C305  100uF  [SM-7351-CAP-smdcan]
C310  100uF  [SM-7351-CAP-smdcan]
C327  10uF  [SM-7351-CAP-0805]
C328  10uF  [SM-7351-CAP-0805]
C330  1uF  [SM-7351-CAP-0402]
C332  10uF  [SM-7351-CAP-0805]
C336  10uF  [SM-7351-CAP-0805]
C339  10uF  [SM-7351-CAP-0805]
C340  10uF  [SM-7351-CAP-0805]
C348  4.7uF  [SM-7351-CAP-0603]
C349  0.1uF  [SM-7351-CAP-0402]
C363  0.1uF  [SM-7351-CAP-0402]
C365  2.2uF  [SM-7351-CAP-0402]
C367  22uF  [SM-7351-CAP-0805]
C368  22uF  [SM-7351-CAP-0805]
C437  1uF  [SM-7351-CAP-0603]
C438  1uF  [SM-7351-CAP-0603]
D1  Green LED  [sm_led_0805]
D2  Green LED  [sm_led_0805]
D3  SMCJ15CA  [SMCJ15CA]
D4  B520C-13-F  [B520C-13-F]
F1  Fuse 4A  [smdfuseblk]
J1  Header 8x2 RA  [HDR2X8RA-201M]
J5  Power Jack RAPC712  [RAPC712]
J25  HEADER 2  [header_2x1]
L5  1.5uH  [IND_SPM3012T]
L6  10uH  [ind-mlz2012-57m]
L7  10uH  [ind-mlz2012-57m]
L8  1.5uH  [IND_SPM3012T]
L9  1.5uH  [IND_SPM3012T]
L10  1.5uH  [IND_SPM3012T]
L11  4.7uH  [smd_slf7055t]
R1  0  [SM-7351-RES-0402]
R2  0  [SM-7351-RES-0402]
R7  0  [SM-7351-RES-1210]
R61  1.4K  [SM-7351-RES-0402]
R70  0  [SM-7351-RES-0402]
R72  2.2K  [sm-7351-res-0402]
R76  0  [SM-7351-RES-0402]
R77  2.2K  [sm-7351-res-0402]
R79  10K  [SM-7351-RES-0402]
R80  0  [SM-7351-RES-0402]
R82  0  [SM-7351-RES-0402]
R83  0  [SM-7351-RES-0402]
R85  10K  [SM-7351-RES-0402]
R87  22K  [SM-7351-RES-0402]
R91  100K  [SM-7351-RES-0402]
R92  10K  [SM-7351-RES-0402]
R93  0  [SM-7351-RES-0402]
R95  10K  [SM-7351-RES-0402]
R96  22K  [SM-7351-RES-0402]
R97  0  [SM-7351-RES-0402]
R98  0  [SM-7351-RES-0402]
R269  150  [SM-7351-RES-0402]
R270  33  [SM-7351-RES-0402]
R304  10K  [SM-7351-RES-0402]
R313  0  [SM-7351-RES-0402]
R327  0  [SM-7351-RES-0603]
R335  0  [SM-7351-RES-0603]
R370  100K  [SM-7351-RES-0402]
R381  1.62M  [SM-7351-RES-0402]
R382  180K  [SM-7351-RES-0402]
R548  1M  [SM-7351-RES-0402]
R549  499K,1%  [SM-7351-RES-0402]
R550  0  [SM-7351-RES-0402]
R551  0  [SM-7351-RES-0402]
SW1  B3SL  [SW_B3SL-1022P]
SW2  Slide Switch  [TH_SW_T551101]
TP3  TP  [TH_TP_5002]
TP4  TP  [TH_TP_5002]
TP9  TP  [TH_TP_5002]
TP10  TP  [TH_TP_5002]
TP11  TP1mm  [tp_smd1mmcircle]
TP20  TP1mm  [tp_smd1mmcircle]
TP21  TP  [TH_TP_5002]
TP23  TP  [TH_TP_5002]
U56  TPS65218  [qfn6x6-48-39m]
U62  TPS63010  [u_20_dsbga]
U76  TPS78101  [sot23-5-43m]
sheet Pg05: NAND Flash Memory & eMMC
C211  0.1uF  [SM-7351-CAP-0402]
C212  10uF  [SM-7351-CAP-0805]
C213  1uF  [SM-7351-CAP-0402]
C215  0.01uF  [SM-7351-CAP-0402]
C216  0.01uF  [SM-7351-CAP-0402]
C217  0.01uF  [SM-7351-CAP-0402]
C218  0.1uF  [SM-7351-CAP-0402]
C219  0.01uF  [SM-7351-CAP-0402]
C220  0.01uF  [SM-7351-CAP-0402]
C221  10uF  [SM-7351-CAP-0805]
C226  0.01uF  [SM-7351-CAP-0402]
C227  0.01uF  [SM-7351-CAP-0402]
C228  0.01uF  [SM-7351-CAP-0402]
C231  0.01uF  [SM-7351-CAP-0402]
C232  0.01uF  [SM-7351-CAP-0402]
C233  0.01uF  [SM-7351-CAP-0402]
C234  0.01uF  [SM-7351-CAP-0402]
C360  0.01uF  [SM-7351-CAP-0402]
C361  0.01uF  [SM-7351-CAP-0402]
C362  0.1uF  [SM-7351-CAP-0402]
C364  0.01uF  [SM-7351-CAP-0402]
R160  10K  [SM-7351-RES-0402]
R170  10K  [SM-7351-RES-0402]
R171  10K  [SM-7351-RES-0402]
R173  0  [SM-7351-RES-0402]
R175  49.9K  [SM-7351-RES-0402]
R176  10K  [SM-7351-RES-0402]
R179  49.9K  [SM-7351-RES-0402]
R180  49.9K  [SM-7351-RES-0402]
R181  49.9K  [SM-7351-RES-0402]
R359  0  [SM-7351-RES-0402]
R364  10K  [SM-7351-RES-0402]
R365  0  [SM-7351-RES-0402]
R366  0  [SM-7351-RES-0402]
R367  0  [SM-7351-RES-0402]
R368  0  [SM-7351-RES-0402]
R369  10K  [SM-7351-RES-0402]
R371  0  [SM-7351-RES-0402]
R383  0  [SM-7351-RES-0402]
R384  0  [SM-7351-RES-0402]
R385  0  [SM-7351-RES-0402]
R401  49.9K  [SM-7351-RES-0402]
R402  49.9K  [SM-7351-RES-0402]
R403  49.9K  [SM-7351-RES-0402]
R404  49.9K  [SM-7351-RES-0402]
U22  SN74LVC1G07  [SC70-5-43M]
U23  SN74AVC8T245  [TSSOP8x4-24-47m]
U25  TXS0108E  [u_20_pw]
U63  MT29F4G08AB  [skt-tsop48sm]
U65  MTFC4GLDDQ-4M IT  [bga18x14-100-55m]
sheet Pg08: SDMMC0 Interface
C13  4.7uF  [SM-7351-CAP-0603]
C17  0.1uF  [SM-7351-CAP-0402]
J7  SCHA5B0200  [SD-MICRO-SCHA5B0300]
R142  0  [SM-7351-RES-0402]
R144  0  [SM-7351-RES-0402]
R147  0  [SM-7351-RES-0402]
R149  0  [SM-7351-RES-0402]
R150  0  [SM-7351-RES-0402]
R152  0  [SM-7351-RES-0402]
R292  470K  [SM-7351-RES-0402]
R293  10K  [SM-7351-RES-0402]
R294  10K  [SM-7351-RES-0402]
R298  10K  [SM-7351-RES-0402]
R309  10K  [SM-7351-RES-0402]
R311  10K  [SM-7351-RES-0402]
R353  0  [SM-7351-RES-0402]
U51  TPD2E001  [U_5_DRL]
U53  TPD6E001  [U_10_RSE]
sheet Pg10: Sensors, Buzzer, Haptics
C6  0.01uF  [SM-7351-CAP-0402]
C155  0.01uF  [SM-7351-CAP-0402]
C244  0.01uF  [SM-7351-CAP-0402]
C245  0.01uF  [SM-7351-CAP-0402]
C271  1uF  [SM-7351-CAP-0603]
J10  HEADER 4  [HDR1x4-330M]
Q1  BSS138  [SOT23-3]
Q4  BSS138  [SOT23-3]
R113  33  [SM-7351-RES-0402]
R114  0  [SM-7351-RES-0402]
R115  2.2K  [sm-7351-res-0402]
R123  0  [SM-7351-RES-0402]
R125  0  [SM-7351-RES-0402]
R127  0  [SM-7351-RES-0402]
R130  10K  [SM-7351-RES-0402]
R131  0  [SM-7351-RES-0402]
R190  0  [SM-7351-RES-0402]
R191  0  [SM-7351-RES-0402]
R222  62,1%  [sm-7351-res-0402]
R235  0  [SM-7351-RES-0402]
R236  1K  [SM-7351-RES-0402]
R354  2.2K  [sm-7351-res-0402]
R355  2.2K  [sm-7351-res-0402]
SPKR1  AudioBuzzer_AI_1027  [spkr_ai_1027]
U1  TSL2550  [smd4x3-4-59m]
U20  TMP275  [MSOP_dgk]
U32  LIS331DLH  [LGA16pin_3x3]
U39  PicoHaptics 304-100  [pico_304-100]
sheet Pg19: Wireless COM8
C246  0.01uF  [SM-7351-CAP-0402]
C247  0.01uF  [SM-7351-CAP-0402]
C254  0.01uF  [SM-7351-CAP-0402]
C256  0.01uF  [SM-7351-CAP-0402]
C413  1uF  [SM-7351-CAP-0402]
C419  2.2uF  [SM-7351-CAP-0805]
C422  15pF  [SM-7351-CAP-0402]
C433  0.01uF  [SM-7351-CAP-0402]
C436  0.01uF  [SM-7351-CAP-0402]
J20  MEC6_100pin  [MEC6-150-02-S-D-RA1]
R189  0  [SM-7351-RES-0402]
R195  0  [SM-7351-RES-0402]
R196  0  [SM-7351-RES-0402]
R241  0  [SM-7351-RES-0402]
R242  10K  [SM-7351-RES-0402]
R243  10K  [SM-7351-RES-0402]
R244  10K  [SM-7351-RES-0402]
R245  10K  [SM-7351-RES-0402]
R246  10K  [SM-7351-RES-0402]
R247  10K  [SM-7351-RES-0402]
R248  0  [SM-7351-RES-0402]
R249  0  [SM-7351-RES-0402]
R250  0  [SM-7351-RES-0402]
R251  0  [SM-7351-RES-0402]
R252  0  [SM-7351-RES-0402]
R253  0  [SM-7351-RES-0402]
R254  0  [SM-7351-RES-0402]
R255  0  [SM-7351-RES-0402]
R256  0  [SM-7351-RES-0402]
R257  0  [SM-7351-RES-0402]
R258  0  [SM-7351-RES-0402]
R436  0  [SM-7351-RES-0402]
R439  30.1K  [SM-7351-RES-0402]
R446  57.6K  [SM-7351-RES-0402]
R452  0  [SM-7351-RES-0402]
R453  0  [SM-7351-RES-0402]
R454  0  [SM-7351-RES-0402]
R455  0  [SM-7351-RES-0402]
R456  0  [SM-7351-RES-0402]
R457  0  [SM-7351-RES-0402]
R489  0  [SM-7351-RES-0402]
R490  0  [SM-7351-RES-0402]
TP5  TP1mm  [tp_smd1mmcircle]
TP6  TP1mm  [tp_smd1mmcircle]
TP7  TP1mm  [tp_smd1mmcircle]
TP8  TP1mm  [tp_smd1mmcircle]
U33  SN74AVC4T245  [U_16_PW]
U34  SN74AVC1T45  [smdsc70-6]
U71  TPS79501  [sot223_6pin]
sheet Pg20: Tamper Oscillator/Ctrl
C96  25pF  [SM-7351-CAP-0603]
C97  25pF  [SM-7351-CAP-0603]
J29  HEADER 2  [header_2x1]
R107  0  [SM-7351-RES-0402]
R326  0  [SM-7351-RES-0402]
R330  0  [SM-7351-RES-0402]
TP13  TP  [TH_TP_5002]
TP14  TP  [TH_TP_5002]
Y3  32.768KHz MC-306  [MC-306]
sheet Pg23: Unused pins/GPIO
C84  0.01uF  [SM-7351-CAP-0402]
C85  0.01uF  [SM-7351-CAP-0402]
J23  HEADER 3x2  [hdr2x3-330m]
J30  Header 20x2  [HDR2X20-330M]
R109  0  [SM-7351-RES-0402]
R117  0  [SM-7351-RES-0402]
R118  0  [SM-7351-RES-0402]
R119  0  [SM-7351-RES-0402]
R120  0  [SM-7351-RES-0402]
R121  0  [SM-7351-RES-0402]
R134  4.7K  [SM-7351-RES-0402]
R351  4.7K  [SM-7351-RES-0402]
R357  0  [SM-7351-RES-0402]
R360  0  [SM-7351-RES-0402]
R450  10K  [SM-7351-RES-0402]
TP15  TP1mm  [tp_smd1mmcircle]
TP16  TP1mm  [tp_smd1mmcircle]
U59  AM437X_ZDN  [AM437X_ZDN]  (sections -1,-10,-11,-12,-13,-14,-15,-16,-17,-18,-19,-2,-20,-21,-22,-23,-24,-25,-3,-4,-5,-6,-7,-8,-9)
sheet Pg27: Power Monitor
C14  0.1uF  [SM-7351-CAP-0402]
C18  0.1uF  [SM-7351-CAP-0402]
C22  0.01uF  [SM-7351-CAP-0402]
C58  0.1uF  [SM-7351-CAP-0402]
C92  0.1uF  [SM-7351-CAP-0402]
C99  0.1uF  [SM-7351-CAP-0402]
C100  0.1uF  [SM-7351-CAP-0402]
C106  0.01uF  [SM-7351-CAP-0402]
C200  0.1uF  [SM-7351-CAP-0402]
C311  4.7uF  [SM-7351-CAP-0603]
C324  0.1uF  [SM-7351-CAP-0402]
C343  4.7uF  [SM-7351-CAP-0603]
J6  HEADER 5  [HEADER_5X1]
J24  HEADER 2  [header_2x1]
J26  HEADER 2  [header_2x1]
J32  HEADER 2  [header_2x1]
J34  HEADER 2  [header_2x1]
R32  4.7K  [SM-7351-RES-0402]
R33  4.7K  [SM-7351-RES-0402]
R40  10K  [SM-7351-RES-0402]
R104  10K  [SM-7351-RES-0402]
U5  INA226  [MSOP3X3-10-43M]
U18  INA226  [MSOP3X3-10-43M]

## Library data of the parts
C59 C213 C330 C373 C413 C431 = 1C_1uFCapacitor10V10%0402
C94 C95 C422 = 1C_15pFCapacitor50V10%smd0402
C180 C186 = 1C_24pFCapacitor50V5%SMD0402
C6 C22 C84 C85 C106 C155 C215-C217 C219 C220 C226-C228 C231-C234 C244-C247 C254 C256 C360 C361 C364 C418 C433 C436 = 1C_0.01uFCapacitor16V10%0402
R40 R69 R75 R79 R85 R92 R95 R104 R130 R137 R160 R170 R171 R176 R242-R247 R293 R294 R298 R304 R309 R311 R344 R364 R369 R450 R466 = 1R_10KOhmResistor1_16W0402
R1 R2 R70 R76 R80 R82 R83 R93 R97 R98 R106-R109 R114 R117-R121 R123 R125 R127 R131 R135 R136 R142-R144 R147 R149 R150 R152 R173 R189-R191 R195 R196 R235 R241 R248-R258 R286 R313 R326 R330 R337 R343 R346 R353 R357 R359 R360 R365-R368 R371 R383-R385 R436 R452-R457 R489 R490 R550 R551 = 1R_ZeroOhmResistor1_16W0402
R140 = 1MOhmResistor1_16W0402
R399 R449 R482 = 1R_100ohm1_16W1%SMD0402
SW1 SW3 SW10 SW13 = 2W_Switch_Pushbuttonsmd
U22 U74 = 1A_SN74LVC1G07
Y2 Y3 = 1Y_Crystal_SMD32_768kHz
Y4 = 1Y_Crystal24MHzSCM
BT1 = 1P_BatteryCR1632Holder
C37 = 1C_220uFCapacitor16V10%Tantalum
C49 C367 C368 = 1C_22uFCapacitor16V10%0805
C13 C54 C61 C65 C69 C75 C76 C79 C311 C343 C348 = 1C_4.7uFCapacitor16V10%0603
C55 C66 = 1C_22uFCapacitor6.3V20%0603
C14 C17 C18 C58 C92 C99 C100 C200 C211 C218 C301 C302 C324 C362 C363 = 1C_0.1uFCapacitor16V10%0402
C271 C303 C437 C438 = 1C_1uFCapacitor50V10%0603
C212 C221 C304 C327 C328 C332 C336 C339 C340 = 1C_10uFCapacitor16V10%0805
C305 C310 = 1C_100uFCapacitor16V20%ElecPoly
C349 = 1C_0.1uFCapacitor16V10%0402: Installed: DNI
C365 = 1C_2.2uFCapacitor6.3V20%X5R0402
D1 D2 = 1F_LED_Green
D3 = 1E_Diode_SMCJ15CA
D4 = 1E_Diode_5ARect
F1 = 1P_Fuse_4A
J1 = 2H_Header8x2pin_RA
J5 = 2J_Conn_PwrJack_RAPC712
J24-J26 J29 J32 J34 = 2H_Header_2x1
L5 L8-L10 = 1L_1.5uHInductor20%2.8Asmd
L6 L7 = 1L_10uHInductor20%110mAsmd
L11 = 1L_4.7uHInductor30%3.1Asmd
R7 = 1R_ZeroOhmResistor1_2W1210
R61 = 1R_1.4KOhmResistor1_16W1%0402
R72 R77 R115 R354 R355 = 1R_2.2KOhmResistor1_16W0402
R87 R96 = 1R_22Kohm1_16W1%SMD0402
R91 R370 = 1R_100KOhmResistor1_16W0402
R269 = 1R_150ohm1_16W1%SMD0402
R113 R270 = 1R_33ohmResistor1_16W5%0402
R327 R335 = 1R_ZeroOhmResistor1_16W0603
R381 = 1R_1.62MOhmResistor1_16W0402
R382 = 1R_180KOhmResistor1_16W0402
R548 = 1R_1MOhmResistor1_16W0402
R549 = 1R_499Kohm1_16W1%smd0402
SW2 = 2W_Switch_SlideRA_SPDT
TP3 TP4 TP9 TP10 TP13 TP14 TP21 TP23 = 2H_TestPointThroughHole
TP5-TP8 TP11 TP15 TP16 TP20 = 2H_Testpoint_SMD1mmCircle
U56 = 1A_TPS65218
U62 = 1A_TPS63010YFF
U76 = 1A_TPS78101
R175 R179-R181 R401-R404 = 1R_49.9KOhmResistor1_16W0402
U23 = 1A_SN74AVC8T245
U25 = 1A_TXS0108
U63 = 1A_MT29F4G08ABAE
U65 = 1A_MTFC4GLDDQ-4M
J7 = 2C_Conn_microSD_8
R292 = 470Kohm1_16W1%SMD0402
U51 = 1A_TPD2E001DRL
U53 = 1A_TPD6E001RSE
J10 = 2H_Header_4x1
Q1 Q4 = 1Q_MOSFET_NChan_BSS138
R222 = 1R_62OhmResistor1_16W0402
R236 = 1R_1KOhmResistor1_16W0402
SPKR1 = 1G_AudioBuzzer_AI_1027
U1 = 1A_TSL2550
U20 = 1A_TMP275
U32 = 1A_LIS331DLH
U39 = 1G_Haptics_Pico_304-100
C419 = 1C_2.2uF16V10%SMD0805
J20 = 2C_Conn_SamtecMEC6_150
R439 = 1R_30.1Kohm1_16W1%smd0402
R446 = 1R_57.6Kohm1_10W1%smd0402
U33 = 1A_SN74AVC4T245
U34 = 1A_SN74AVC1T45
U71 = 1A_TPS79501
C96 C97 = 1C_25pFCapacitor100V5%0603
J23 = 2H_Header3x2
J30 = 2H_Header20x2
R32 R33 R134 R351 = 1R_4.7KOhmResistor1_16W0402
U59 = am437x_zdn_GPEVM
J6 = 2H_Header_5x1
U5 U18 = 1A_INA226

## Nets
DGND: BT1.2(Neg) C6.2 C13.2 C17.2 C18.2 C22.2 C37.2(NEG) C49.2 C54.2 C55.2 C59.2 C61.2 C65.2 C66.2 C69.2 C75.2 C76.2 C79.2 C84.2 C85.2 C96.1 C97.1 C100.2 C106.2 C155.2 C211.2 C212.2 C213.2 C215.2 C216.2 C217.2 C218.2 C219.2 C220.2 C221.2 C226.2 C227.2 C228.2 C231.2 C232.2 C233.2 C234.2 C244.2 C245.2 C246.2 C247.2 C254.2 C256.2 C271.2 C301.2 C302.2 C303.2 C304.2 C305.2(NEG) C310.2(NEG) C311.2 C327.2 C328.2 C330.2 C332.2 C336.2 C339.2 C340.2 C343.2 C348.2 C349.2 C360.2 C361.2 C362.2 C363.2 C364.2 C365.2 C367.2 C368.2 C373.2 C413.2 C418.2 C419.2 C431.2 C433.2 C436.2 C437.2 C438.2 D1.1(Cathode) D2.1(Cathode) D3.2(ANODE) J1.9 J1.15 J1.16 J5.2 J5.3 J6.3 J7.6(VSS) J7.9(GND) J7.11(GND3) J7.12(GND4) J7.13(GND5) J7.14(GND6) J7.15(GND7) J7.16(GND8) J10.4 J20.2 J20.3 J20.6 J20.9 J20.18 J20.19 J20.22 J20.35 J20.37 J20.39 J20.42 J20.47 J20.60 J20.63 J20.64 J20.77 J20.83 J20.87 J20.92 J20.95 J20.97 J23.5 J23.6 J30.12 J30.39 J30.40 Q1.S(SOURCE) Q4.S(SOURCE) R87.1(P1) R91.1(P1) R97.1(P1) R115.1(P1) R127.1(P1) R131.1(P1) R176.1(P1) R189.1(P1) R190.1(P1) R195.1(P1) R236.1(P1) R286.2(P2) R326.1(P1) R330.1(P1) R344.1(P1) R382.1(P1) R439.1(P1) R548.1(P1) SW1.1 SW1.2 SW2.M1 SW2.M2 SW3.1 SW3.2 SW10.1 SW10.2 SW13.1 SW13.2 TP3.1 TP4.1 TP9.1 TP23.1 U1.2(GND) U5.1(A1) U5.2(A0) U5.7(GND) U18.1(A1) U18.7(GND) U20.4(GND) U20.5(A2) U22.3(GND) U23.11(GND) U23.12(GND) U23.13(GND) U25.11(GND) U32.5(GND) U32.10(RSV0) U32.12(GND) U32.13(GND) U32.16(GND) U33.8(GND) U33.9(GND) U33.14(2~{OE}) U33.15(1~{OE}) U34.2(GND) U39.M1 U39.M2 U51.4(GND) U53.5(GND) U56.TPAD(GNDP) U62.B4(SYNC) U62.C1(PGND) U62.C2(PGND) U62.C3(GND) U62.D3(GND) U62.E4(GND) U63.13(GND) U63.25(GND) U63.36(GND) U63.48(GND) U65.G2(VSS) U65.G3(VSS) U65.G4(VSS) U65.G5(VSS) U65.G6(VSS) U65.G7(VSS) U65.G8(VSS) U65.G9(VSS) U65.H2(VSSQ) U65.H9(VSSQ) U65.L3(VSSQ) U65.L8(VSSQ) U65.M4(VSSQ) U65.M7(VSSQ) U65.P2(VSSQ) U65.P9(VSSQ) U71.3(GND) U71.6(GND) U74.3(GND) U76.2(GND) ; also on sheet 1 2 3 5 6 7 8 9 10 11 12 14 15 16 17 18
GND_OSC0: C180.2 C186.2 R286.1(P1) U59.B24(VSS_OSC)
GND_OSC1: C94.2 C95.2 U59.AD4(VSS_RTC)
V1_0BAT: C66.1 L7.2 U56.21(FB5) ; also on sheet 18
V1_8BAT: C438.1 R79.2(P2) R549.2(P2) R550.1(P1) U76.5(OUT) ; also on sheet 18
V1_8D: C254.1 C256.1 C433.1 J20.8 J20.62 R75.2(P2) R196.1(P1) R242.2(P2) R243.2(P2) R244.2(P2) R245.2(P2) R246.2(P2) R247.2(P2) R335.1(P1) R364.2(P2) R436.2(P2) U22.5(VCC) U33.1(VCCA) U34.1(VCCA) ; also on sheet 4 5 6 18
V3_3D: C6.1 C13.1 C17.1 C22.1 C84.1 C106.1 C155.1 C211.1 C212.1 C215.1 C216.1 C217.1 C218.1 C219.1 C220.1 C221.1 C226.1 C227.1 C228.1 C231.1 C232.1 C233.1 C234.1 C244.1 C245.1 C246.1 C247.1 C311.1 C343.1 C360.1 C361.1 C362.1 C364.1 J7.4(VDD) J10.1 J30.1 R32.2(P2) R33.2(P2) R40.2(P2) R69.2(P2) R72.2(P2) R77.2(P2) R92.2(P2) R104.2(P2) R130.2(P2) R134.2(P2) R137.2(P2) R160.2(P2) R170.2(P2) R171.2(P2) R175.2(P2) R179.2(P2) R180.2(P2) R181.2(P2) R191.2(P2) R270.2 R292.2(P2) R293.2(P2) R294.2(P2) R298.2(P2) R309.2(P2) R311.2(P2) R327.1(P1) R351.2(P2) R354.2(P2) R355.2(P2) R369.1(P1) R370.2(P2) R401.2(P2) R402.2(P2) R403.2(P2) R404.2(P2) R450.2(P2) R466.2(P2) U1.1(VDD) U5.6(VS) U18.6(VS) U20.8(V+) U23.1(VCCA) U23.23(VCCB) U23.24(VCCB) U25.2(VCCA) U25.19(VCCB) U32.1(VDD_IO) U32.14(VDD) U32.15(RSV1) U33.16(VCCB) U34.6(VCCB) U51.1(VCC) U53.10(VCC) U63.12(VCC) U63.34(VCC) U63.37(VCC) U63.39(VCC) U65.F2(VCC) U65.F3(VCC) U65.F4(VCC) U65.F5(VCC) U65.F6(VCC) U65.F7(VCC) U65.F8(VCC) U65.F9(VCC) U65.H3(VCCQ) U65.H8(VCCQ) U65.L2(VCCQ) U65.L4(VCCQ) U65.L7(VCCQ) U65.L9(VCCQ) U65.P3(VCCQ) U65.P8(VCCQ) ; also on sheet 1 2 3 5 6 7 8 9 10 12 14 15 16 17 18
V5_0D: C365.1 C367.1 C368.1 R381.2(P2) U56.32(IN_LS2) U62.E1(VOUT) U62.E2(VOUT) ; also on sheet 3 16 17
V5_0D_EN: R370.1(P1) U62.A4(EN)
VBAT: C37.1(POS) C61.1 C65.1 C69.1 C75.1 C76.1 C79.1 C85.1 C348.1 C349.1 C413.1 J1.2 J1.4 J30.2 R7.1(P1) R85.2(P2) R95.2(P2) R96.2(P2) R113.2 R222.2(P2) U56.1(IN_DCDC1) U56.5(IN_LDO1) U56.12(IN_DCDC4) U56.27(IN_BU) U56.36(IN_BIAS) U56.37(IN_DCDC3) U56.43(IN_DCDC2) U62.A1(VIN) U62.A2(VIN) U71.2(IN) ; also on sheet 1 3 4 5 9 10 11
VBAT1_SW: TP21.1 U56.7(LS3)
VINT_LDO: C49.1 C418.1 U56.35(INT_LDO) U74.5(VCC)
ACCEL_INT1: R119.2(P2) U32.11(INT1)
ACCEL_INT2: R109.2(P2) U32.9(INT2)
AM437X_AIN7: R2.1(P1) ; also on sheet 4
AM437X_COM_BTRST: R489.2(P2) U59.C3(GPMC_A0/GPIO)
AM437X_COM_PPSOUT: R250.1(P1) U59.E7(GPMC_A5/GPIO)
AM437X_COM_TIMESTAMP: R249.1(P1) U59.E8(GPMC_A6/GPIO)
AM437X_COM_WLANIRQ: R248.1(P1) U59.F6(GPMC_A7/GPIO)
AM437X_COM_WLRST: R241.1(P1) U59.D7(GPMC_A4/GPIO)
AM437X_CSN1: R366.2(P2) U59.B9(GPMC_CSN1/MMC1_CLK)
AM437X_CSN2: R368.2(P2) U59.F10(GPMC_CSN2/MMC1_CMD)
AM437X_HDMI_INTn: U59.N20(SPI2_SCLK) ; also on sheet 3
AM437X_HDQ_MONITOR: J30.19 R1.1(P1) U59.AB25(CAM1_WEN)
AM437X_I2C1_SCL: R125.1(P1) R355.1(P1) U59.T20(SPI0_CS0/I2C1_SCL)
AM437X_I2C1_SDA: R123.1(P1) R354.1(P1) U59.T21(SPI0_D1/I2C1_SDA)
AM437X_KEY_PWRA: J30.7 U59.K23(MCASP0_FSR/GPIO) ; also on sheet 11
AM437X_KEY_PWRB: J30.9 U59.M25(MCASP0_AXR1/GPIO) ; also on sheet 11
AM437X_KEY_SCN0: J30.3 U59.L24(MCASP0_AHCLKX/GPIO) ; also on sheet 11
AM437X_KEY_SCN1: J30.11 U59.AD17(CAM0_WEN) ; also on sheet 11
AM437X_KEY_SCN2: J30.13 U59.AC18(CAM0_FIELD) ; also on sheet 11
AM437X_MMC0_CLK: R152.2(P2) U59.D1(MMC0_CLK)
AM437X_MMC0_CMD: R150.2(P2) U59.D2(MMC0_CMD)
AM437X_MMC0_DAT0: R149.2(P2) U59.C1(MMC0_DAT0)
AM437X_MMC0_DAT1: R147.2(P2) U59.C2(MMC0_DAT1)
AM437X_MMC0_DAT2: R144.2(P2) U59.B2(MMC0_DAT2)
AM437X_MMC0_DAT3: R142.2(P2) U59.B1(MMC0_DAT3)
AM437X_MMC0_SDCD: R353.2(P2) U59.R25(SPI0_CS1/MMC0_SDCD)
AM437X_NAND_AD0: U23.3(A1) U25.1(A1) U59.B5(GPMC_AD0)
AM437X_NAND_AD1: U23.4(A2) U25.3(A2) U59.A5(GPMC_AD1)
AM437X_NAND_AD2: U23.5(A3) U25.4(A3) U59.B6(GPMC_AD2)
AM437X_NAND_AD3: U23.6(A4) U25.5(A4) U59.A6(GPMC_AD3)
AM437X_NAND_AD4: U23.7(A5) U25.6(A5) U59.B7(GPMC_AD4)
AM437X_NAND_AD5: U23.8(A6) U25.7(A6) U59.A7(GPMC_AD5)
AM437X_NAND_AD6: U23.9(A7) U25.8(A7) U59.C8(GPMC_AD6)
AM437X_NAND_AD7: U23.10(A8) U25.9(A8) U59.B8(GPMC_AD7)
AM437X_NAND_WPn: R359.2(P2) U59.B3(GPMC_WPn)
AM437X_NMIn: C431.1 R93.1(P1) R466.1(P1) SW3.3 SW3.4 U59.G25(NMIn)
AM437X_OSC0_IN: R143.1(P1) U59.C25(OSC0_IN)
AM437X_OSC0_OUT: R135.1(P1) U59.B25(OSC0_OUT)
AM437X_PORZn: R108.1(P1) U59.Y23(PORZn)
AM437X_STATUS_LED0: J30.5 U59.L23(MCASP0_ACLKR/GPIO) ; also on sheet 11
AM437X_STATUS_LED1: J30.23 R134.1(P1) U59.N23(JTAG_EMU0) ; also on sheet 10 11
AM437X_STATUS_LED2: J30.25 R351.1(P1) U59.T24(JTAG_EMU1) ; also on sheet 10 11
AM437X_STATUS_LED3: J30.31 U59.G20(GPIO5_10) ; also on sheet 11
AM437X_STATUS_LED4: J30.33 U59.F23(GPIO5_11) ; also on sheet 11
AM437X_STATUS_LED5: J30.35 U59.E25(GPIO5_12) ; also on sheet 11
AM437X_STATUS_LED6: J30.37 U59.E24(GPIO5_13) ; also on sheet 11
AM437X_STATUS_LED7: J30.22 U59.P25(GPIO5_4) ; also on sheet 11
BAT_HDQ: J1.13 R1.2(P2)
BUZZER_N: Q1.D(DRAIN) SPKR1.2(NEG-)
BUZZER_P: R113.1 SPKR1.1(POS+)
COM_AUD_CLK: J20.52 R251.2(P2)
COM_AUD_FSYNC: J20.54 R252.2(P2)
COM_AUD_IN: J20.56 R253.2(P2)
COM_AUD_OUT: J20.58 R254.2(P2)
COM_BTRST: J20.89 R489.1(P1)
COM_BTUARTCTS: J20.70 R257.2(P2)
COM_BTUARTDEBUG: J20.76 TP5.1
COM_BTUARTRTS: J20.72 R258.2(P2)
COM_BTUARTRX: J20.68 R256.2(P2)
COM_BTUARTTX: J20.66 R255.2(P2)
COM_GNSS_PPS_OUT: J20.50 R250.2(P2)
COM_GNSS_TIME_STAMP: J20.48 R249.2(P2)
COM_SDIO_CLK: J20.20 R242.1(P1) R457.2(P2)
COM_SDIO_CMD: J20.24 R243.1(P1) R456.2(P2)
COM_SDIO_D0: J20.26 R244.1(P1) R455.2(P2)
COM_SDIO_D1: J20.28 R245.1(P1) R454.2(P2)
COM_SDIO_D2: J20.30 R246.1(P1) R453.2(P2)
COM_SDIO_D3: J20.32 R247.1(P1) R452.2(P2)
COM_SLOW_CLK: J20.1 R490.1(P1)
COM_WL_IRQ: J20.34 R248.2(P2)
COM_WL_RS232_RX: J20.13 TP7.1
COM_WL_RS232_TX: J20.11 TP8.1
COM_WL_RST: J20.4 R241.2(P2)
COM_WL_UART_DBG: J20.15 TP6.1
CTPM_TESTOUT: TP15.1 U59.AD11(RSV)
EMMC_DAT0: R181.1(P1) U25.20(B1) U65.K2(DAT0)
EMMC_DAT1: R180.1(P1) U25.18(B2) U65.N2(DAT1)
EMMC_DAT2: R179.1(P1) U25.17(B3) U65.K3(DAT2)
EMMC_DAT3: R401.1(P1) U25.16(B4) U65.N3(DAT3)
EMMC_DAT4: R404.1(P1) U25.15(B5) U65.N8(DAT4)
EMMC_DAT5: R402.1(P1) U25.14(B6) U65.K8(DAT5)
EMMC_DAT6: R175.1(P1) U25.13(B7) U65.N9(DAT6)
EMMC_DAT7: R403.1(P1) U25.12(B8) U65.K9(DAT7)
EMMC_RSTn: R173.2(P2) U65.M5(RSTn)
EP_PIO_0: J23.1 U59.AC12(RSV)
EP_PIO_1: J23.3 U59.AC10(RSV)
EP_PIO_2: J23.2 U59.AB10(RSV)
EP_PIO_3: J23.4 U59.AA10(RSV)
GP_I2C_SCL: J10.2 J30.24 R80.2(P2) R125.2(P2) U1.3(SMBCLK) U20.2(SCL) U32.4(SCL/SPC) ; also on sheet 3 5 6 9
GP_I2C_SDA: J10.3 J30.26 R70.2(P2) R123.2(P2) U1.4(SMBDATA) U20.1(SDA) U32.6(SDA/SDI/SDO) ; also on sheet 3 5 6 9
GPIO7: J30.17 U59.T22(SPI0_D0/GPIO)
GPIO12: J30.27 R360.1(P1) U59.D25(GPIO5_8)
GPIO13: J30.29 R357.1(P1) U59.F24(GPIO5_9)
GPIO19: J30.28 R118.1(P1) U59.R24(GPIO5_5)
GPIO20: J30.30 R119.1(P1) U59.P24(GPIO5_6)
GPIO21: J30.32 R120.1(P1) U59.N25(GPIO5_7)
GPIO23: J30.36 R109.1(P1) U59.P20(SPI2_D1)
GPIO24: J30.38 R121.1(P1) U59.T23(SPI2_CS0)
GPIO_AUDIO_BUZZER_TRIG: J30.21 R114.1(P1) U59.AC25(CAM1_FIELD)
GPIO_HAPTICS_TRIG: J30.15 R235.1(P1) U59.P23(SPI0_SCLK/GPIO)
GPIO_VTTEN: R120.2(P2) ; also on sheet 12
HAPTICS_N: Q4.D(DRAIN) U39.2(N-)
HAPTICS_P: C271.1 R222.1(P1) U39.1(P+)
I2C0_SCL: R77.1(P1) R80.1(P1) U56.3(SCL) U59.Y22(I2C_SCL0) ; also on sheet 1 14
I2C0_SDA: R70.1(P1) R72.1(P1) U56.2(SDA) U59.AB24(I2C_SDA0) ; also on sheet 1 14
LOWPOWERn: R117.2(P2) R450.1(P1) ; also on sheet 3
MMC_CD: J7.10(CD) R292.1(P1) R353.1(P1) U51.3(IO1)
MMC_CLK: J7.5(CLOCK) R152.1(P1) U53.1(IO1)
MMC_CMD: J7.3(CMD) R150.1(P1) R294.1(P1) U53.7(IO5)
MMC_D0: J7.7(DAT0) R149.1(P1) R309.1(P1) U53.2(IO2)
MMC_D1: J7.8(DAT1) R147.1(P1) R311.1(P1) U53.3(IO3)
MMC_D2: J7.1(DAT2) R144.1(P1) R293.1(P1) U53.6(IO4)
MMC_D3: J7.2(CD/DAT3) R142.1(P1) R298.1(P1) U53.8(IO6)
NAND_ADVN_ALE: R384.1(P1) U63.17(ALE)
NAND_BE0n_CLE: R383.1(P1) U63.16(CLE)
NAND_CSn: R160.1(P1) R371.1(P1) U63.9(\\~{CE})
NAND_D0: U23.21(B1) U63.29(I/O0)
NAND_D1: U23.20(B2) U63.30(I/O1)
NAND_D2: U23.19(B3) U63.31(I/O2)
NAND_D3: U23.18(B4) U63.32(I/O3)
NAND_D4: U23.17(B5) U63.41(I/O4)
NAND_D5: U23.16(B6) U63.42(I/O5)
NAND_D6: U23.15(B7) U63.43(I/O6)
NAND_D7: U23.14(B8) U63.44(I/O7)
NAND_OEn: R367.1(P1) U23.2(DIR) U63.8(\\~{R}E)
NAND_WAIT: R364.1(P1) R365.1(P1) U63.7(R~{/B})
NAND_WEn: R385.1(P1) U63.18(\\~{W}E)
NAND_WPn: R170.1(P1) R171.1(P1) R173.1(P1) U22.4(Y) U63.19(\\~{W}P)
OSC0_IN: C186.1 R140.2(P2) R143.2(P2) Y4.3
OSC0_OUT: C180.1 R135.2(P2) R140.1(P1) Y4.1
PM_ALERT: J6.4 R40.1(P1) U5.3(ALERT) U18.3(ALERT)
PM_AM437X_V1_8DN: C58.2 J26.2 ; also on sheet 18
PM_AM437X_V1_8DP: C58.1 J26.1 ; also on sheet 18
PM_AM437X_V3_3DN: C200.2 J34.2 ; also on sheet 18
PM_AM437X_V3_3DP: C200.1 J34.1 ; also on sheet 18
PM_VDDCOREN: C14.2 U5.9(VIN-) ; also on sheet 18
PM_VDDCOREP: C14.1 U5.10(VIN+) ; also on sheet 18
PM_VDDMPUN: C92.2 U18.9(VIN-) ; also on sheet 18
PM_VDDMPUP: C92.1 U18.10(VIN+) ; also on sheet 18
PM_VDDSAM437XDDRN: C99.2 J32.2 ; also on sheet 18
PM_VDDSAM437XDDRP: C99.1 J32.1 ; also on sheet 18
PM_VDDSDDRN: C324.2 J24.2 ; also on sheet 12
PM_VDDSDDRP: C324.1 J24.1 ; also on sheet 12
PMIC_AC_DET: J1.14 R95.1(P1) R97.2(P2) U56.9(AC_DET)
PMIC_IN_nCC: R83.2(P2) U56.18(IN_nCC)
PMIC_INTn: R92.1(P1) R93.2(P2) U56.45(INTn)
PMIC_L5: L7.1 U56.20(L5)
PMIC_L6: L6.1 U56.23(L6)
PMIC_LDO1: C340.1 R335.2(P2) U56.4(LDO1)
PMIC_PFI: R91.2(P2) R96.1(P1) U56.16(PFI)
PMIC_PGOOD: R98.2(P2) U56.8(PGOOD)
PMIC_PGOODBU: R82.2(P2) U56.19(PGOOD_BU)
PMIC_PWR_EN: R346.1(P1) U56.46(PWR_EN)
PMIC_SYS_BU: C330.1 R551.2(P2) U56.24(SYS_BU)
PMIC_WAKEUPn: R76.2(P2) R79.1(P1) U56.40(WAKEUPn)
PMU_PORZn: J1.5 R75.1(P1) R82.1(P1) R337.1(P1)
PORZn: C59.1 R69.1(P1) R98.1(P1) R108.2(P2) R482.2(P2) U74.2(A)
PWRMON_I2CSCL: J6.1 R33.1(P1) U5.5(SCL) U18.5(SCL)
PWRMON_I2CSDA: J6.2 R32.1(P1) U5.4(SDA) U18.4(SDA)
SEL_eMMCORNANDn: R121.2(P2) R176.2(P2) U23.22(~{OE}) U25.10(OE)
SEL_LCDORHDMIn: R360.2(P2) ; also on sheet 3 5
SYS_RESETn: R449.1(P1) ; also on sheet 3 5 10 14 15
SYS_WARMRESETn: C373.1 R136.2(P2) R137.1(P1) R399.1(P1) R449.2(P2) U74.4(Y)
TEMPSENSOR_ALERT: R118.2(P2) R130.1(P1) U20.3(ALERT)
TM_TESTOUT: TP16.1 U59.AD10(RSV)
TOUCH_INTn: J30.34 U59.P22(SPI2_D0) ; also on sheet 5
USB0_VBUS_DET: R357.2(P2) ; also on sheet 16
USB5V_FB: R381.1(P1) R382.2(P2) U62.E3(FB)
VCOM_BAT: C419.1 C422.1 C436.1 J20.5 J20.7 R446.2 U71.4(OUT)
VCOM_BATEN: R436.1(P1) U71.1(EN)
VCOM_BATFB: C422.2 R439.2(P2) R446.1 U71.5(FB)
VDCDC1: C18.1 C339.1 L9.2 U5.8(VBUS) U56.47(FB1) ; also on sheet 18
VDCDC2: C100.1 C332.1 L8.2 U18.8(VBUS) U56.41(FB2) ; also on sheet 18
VDCDC3: C327.1 L5.2 R304.2(P2) U56.31(IN_LS1) U56.39(FB3) ; also on sheet 12
VDCDC4: C336.1 R327.2(P2) U56.15(DCDC4)
VLS1: C328.1 U56.30(LS1) ; also on sheet 18
VPMIC_LS2: R313.2(P2) U56.33(LS2)
VPWR_IN: C301.1 C302.1 C303.1 C304.1 C305.1(POS) C310.1(POS) J1.1 J1.3 R7.2(P2) R269.2(P2) SW2.2 TP10.1 U56.6(IN_LS3)
VPWRIN_FUSED: D3.1(CATHODE) F1.2 SW2.1
VPWRIN_JCK: D4.2(ANODE) J5.1
VPWRIN_PREFUSE: D4.1(CATHODE) F1.1
VUSB_VBUS0: R313.1(P1) ; also on sheet 16
WAKEUP0: R76.1(P1) R343.1(P1)
N10692191: R399.2(P2) SW13.3 SW13.4
N11290910: R136.1(P1) U59.G22(RESETIN_OUTn)
N11520122: TP13.1 U59.AD7(RSV)
N11520158: C97.2 R107.2(P2) Y3.1
N11520166: R107.1(P1) U59.AE12(RSV)
N11520178: C96.2 U59.AE11(RSV) Y3.4
N11520288: R330.2(P2) U59.AE10(VSS)
N11520324: TP14.1 U59.AE7(RSV)
N11854504: R482.1(P1) SW10.3 SW10.4
N12221112: R191.1(P1) U32.8(CS)
N12221116: R190.2(P2) U32.7(SDO/SA0)
N12369102: J29.1 U59.AD1(VSS)
N12686071: R371.2(P2) U59.A8(GPMC_CS0n)
N12686075: R384.2(P2) U59.A9(GPMC_ADVN_ALE)
N12686079: R367.2(P2) U59.E10(GPMC_OEN_REN)
N12686083: R385.2(P2) U59.D10(GPMC_WEN/GPIO)
N12686087: R383.2(P2) U59.C10(GPMC_BE0N_CLE)
N12686111: R365.2(P2) U59.A2(GPMC_WAIT0)
N12733905: R127.2(P2) U20.7(A0)
N12733913: R131.2(P2) U20.6(A1)
N12734329: Q1.G(GATE) R114.2(P2) R115.2(P2)
N12734771: Q4.G(GATE) R235.2(P2) R236.2(P2)
N14179015: R104.1(P1) U18.2(A0)
N14563512: R85.1(P1) SW1.3 SW1.4 U56.44(PB)
N14564060: C55.1 L6.2 R550.2(P2) U56.22(FB6)
N14564212: C54.1 J25.2 R61.2 U56.25(CC)
N14564240: BT1.1(Pos) J25.1 R61.1
N14564626: TP20.1 U56.11(GPIO1)
N14564630: R304.1(P1) TP11.1 U56.34(GPO2)
N14564740: R87.2(P2) U56.17(DC34_SEL)
N14565284: L10.1 U56.13(L4A)
N14565288: L5.1 U56.38(L3)
N14565304: L8.1 U56.42(L2)
N14565320: L9.1 U56.48(L1)
N14565872: L10.2 U56.14(L4B)
N14568234: L11.1 U62.B1(L1) U62.B2(L1)
N14568254: L11.2 U62.D1(L2) U62.D2(L2)
N14568274: C363.1 U62.A3(VINA) U62.B3(VINA1) U62.C4(~{PS}) U62.D4(VSEL)
N14677780: R359.1(P1) U22.2(A)
N14699899: R366.1(P1) U65.P6(CLK)
N14699960: R368.1(P1) R369.2(P2) U65.P5(CMD)
N14719514: D2.2(Anode) R269.1(P1)
N14719805: D1.2(Anode) R270.1
N15715520: R457.1(P1) U59.A12(GPMC_CLK/MMC2_CLK)
N15715532: R456.1(P1) U59.B12(GPMC_CSN3/MMC2_CMD)
N15715544: R455.1(P1) U59.C5(GPMC_A1/MMC2_DAT0)
N15715556: R454.1(P1) U59.C6(GPMC_A2/MMC2_DAT1)
N15715568: R453.1(P1) U59.A4(GPMC_A3/MMC2_DAT2)
N15715580: R452.1(P1) U59.A3(GPMC_BE1n/MMC2_DAT3)
N15715840: R251.1(P1) U59.F7(GPMC_A8/MCASP0_ACLKX)
N15715852: R253.1(P1) U59.G8(GPMC_A10/MCASP0_AXR0)
N15715864: R254.1(P1) U59.D8(GPMC_A11/MCASP0_AXR1)
N15717058: R252.1(P1) U59.B4(GPMC_A9/MCASP0_FSX)
N15717194: U33.13(1B1) U59.H24(UART3_TXD)
N15717226: U33.11(2B1) U59.H25(UART3_RXD)
N15717266: U33.10(2B2) U59.H22(UART3_CTSn)
N15717730: R490.2(P2) U34.3(A)
N16155764: J30.14 U59.N24(MCASP0_ACLKX/SPI1_SCLK)
N16155776: J30.16 U59.N22(MCASP0_FSX/SPI1_D0)
N16155788: J30.18 U59.H23(MCASP0_AXR0/SPI1_D1)
N16155800: J30.20 U59.M24(MCASP0_AHCLKR/SPI1_CS0)
N16755717: R255.1(P1) U33.6(2A1)
N16755735: R256.1(P1) U33.4(1A1)
N16755741: R257.1(P1) U33.5(1A2)
N16755753: R258.1(P1) U33.7(2A2)
N16756587: U34.4(B) U59.C24(XDMA_EVENT_INTR1/CLKOUT2)
N16927149: C213.1 U65.E4(VDDIM)
N17340566: J1.11 R2.2(P2)
N17746486: R189.2(P2) U34.5(DIR)
N17747795: R195.2(P2) U33.2(1DIR)
N17748019: R196.2(P2) U33.3(2DIR)
N17748257: U33.12(1B2) U59.K24(UART3_RTSn)
N17832251: R106.1(P1) U59.AE4(OSC1_OUT)
N17832253: C94.1 R106.2(P2) Y2.4
N17832259: C95.1 U59.AE5(OSC1_IN) Y2.1
N17957689: R344.2(P2) U59.AE2(RTC_KALDO_EN)
N17957695: R346.2(P2) U59.AD6(RTC_PMIC_EN)
N17957723: R343.2(P2) U59.AE3(RTC_WAKEUP)
N17957870: R337.2(P2) U59.AE6(RTC_PORZ)
N17986228: J29.2 U59.AD2(VSS)
N18289721: R326.2(P2) U59.AE8(VSS)
N18994118: R117.1(P1) U59.H20(CLKREQ/GPIO0_24)
N19255466: C437.1 R551.1(P1) U76.1(IN) U76.3(EN)
N19255489: R548.2(P2) R549.1(P1) U76.4(FB)

Not connected (* = marked no-connect by the designer): J1 6* 7* 8* 10* 12*; J6 5; J20 10 12 14 16 17 21 23 25 27 29 31 33 36 38 40 41 43 44 45 46 49 51 53 55 57 59 61 65 67 69 71 73 74 75 78 79 80 81 82 84 85 86 88 90 91 93 94 96 98 99 100; J30 4 6 8 10; R83 1(P1)*; SW2 3*; U22 1(NC); U32 2(NC0) 3(NC1); U51 2(NC)* 5(IO2); U53 4(NC1)* 9(NC2)*; U56 10(PFOn)* 26(GPIO3) 28(RSV1)* 29(RSV2)*; U59 AA7(RSV) AA9(RSV) AB6(RSV) AB7(RSV) AB9(RSV)* AC5(RSV) AC6(RSV) AC7(RSV)* AC9(RSV) AE9(RSV) H19(RSV) W10(RSV)* Y6(RSV)* Y7(RSV) Y10(RSV); U63 1(NC-1)* 2(NC-2)* 3(NC-3)* 4(NC-4)* 5(NC-5)* 6(NC-6)* 10(NC-7)* 11(NC-8)* 14(NC-9)* 15(NC-10)* 20(NC-11)* 21(NC-12)* 22(NC-13)* 23(NC-14)* 24(NC-15)* 26(NC_IO8) 27(NC_IO9) 28(NC_IO10) 33(NC_IO11) 35(NC16)* 38(NC17)* 40(NC_IO12) 45(NC_IO13) 46(NC_IO14) 47(NC_IO15); U65 A1(NCA1) A2(NCA2) A9(NCA9) A10(NCA10) B1(NCB1) B10(NCB10) D2(NCD2) D3(NCD3) D4(NCD4) D5(NCD5) D6(NCD6) D7(NCD7) D8(NCD8) D9(NCD9) E2(NCE2) E3(NCE3) E5(NCE5) E6(NCE6) E7(NCE7) E8(NCE8) E9(NCE9) H4(NCH4) H5(NCH5) H6(NCH6) H7(NCH7) J2(NCJ2) J3(NCJ3) J4(NCJ4) J5(NCJ5) J6(NCJ6) J7(NCJ7) J8(NCJ8) J9(NCJ9) K4(NCK4) K5(NCK5) K6(NCK6) K7(NCK7) L5(NCL5) L6(NCL6) M2(NCM2) M3(NCM3) M6(NCM6) M8(NCM8) M9(NCM9) N4(NCN4) N5(NCN5) N6(NCN6) N7(NCN7) P4(NCP4) P7(NCP7) T1(NCT1) T10(NCT10) U1(NCU1) U2(NCU2) U9(NCU9) U10(NCU10); U74 1(NC)*; Y2 2* 3*; Y3 2* 3*; Y4 2(NC0)* 4(NC1)*

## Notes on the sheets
sheet 21
- Main Power Input
- Battery Board
  Connector
- Coin Cell
sheet 22
- User Interrupt Switch
- Reset Switch
- Warm Reset Switch
sheet 23
- SD/MMC0 Connector
sheet 25
- NAND Memory
- eMMC Memory
